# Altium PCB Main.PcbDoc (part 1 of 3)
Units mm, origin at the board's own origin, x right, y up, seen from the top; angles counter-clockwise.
Board outline 160.02 x 109 mm, 4 copper layers (Top Layer, MidLayer1, MidLayer2, Bottom Layer), stack 1.588 mm thick; 321 components, 271 nets, 1178 pads, 515 vias.
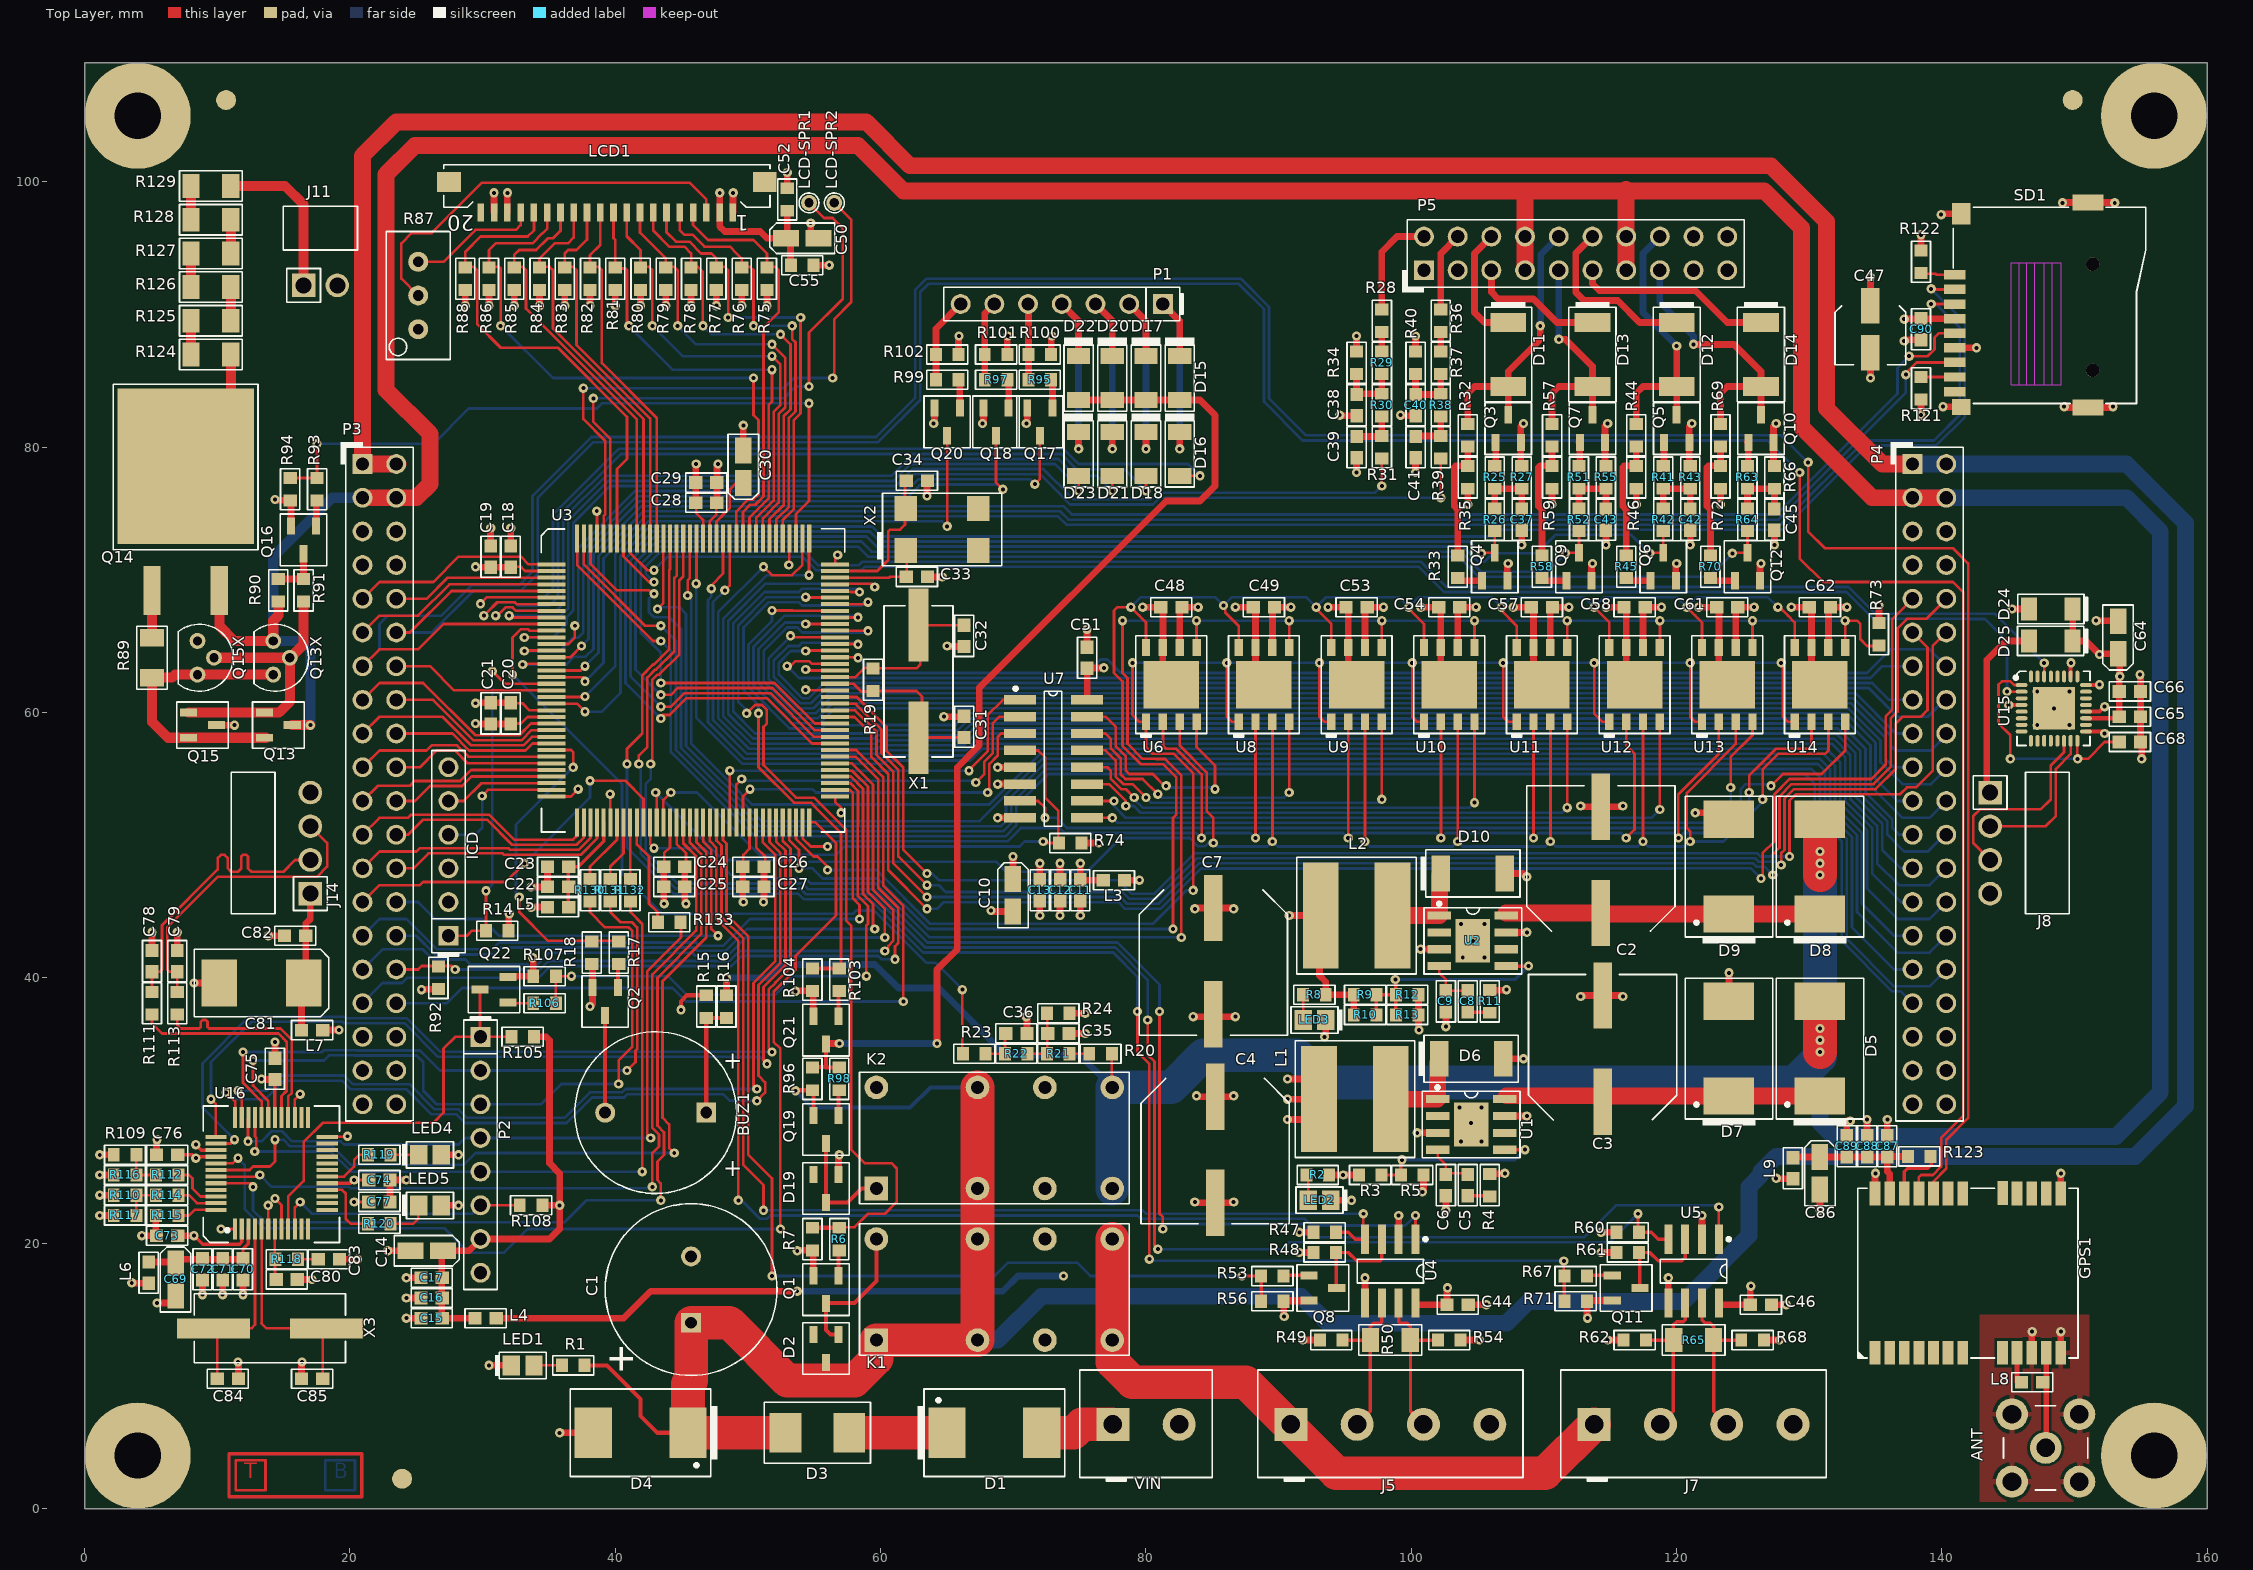
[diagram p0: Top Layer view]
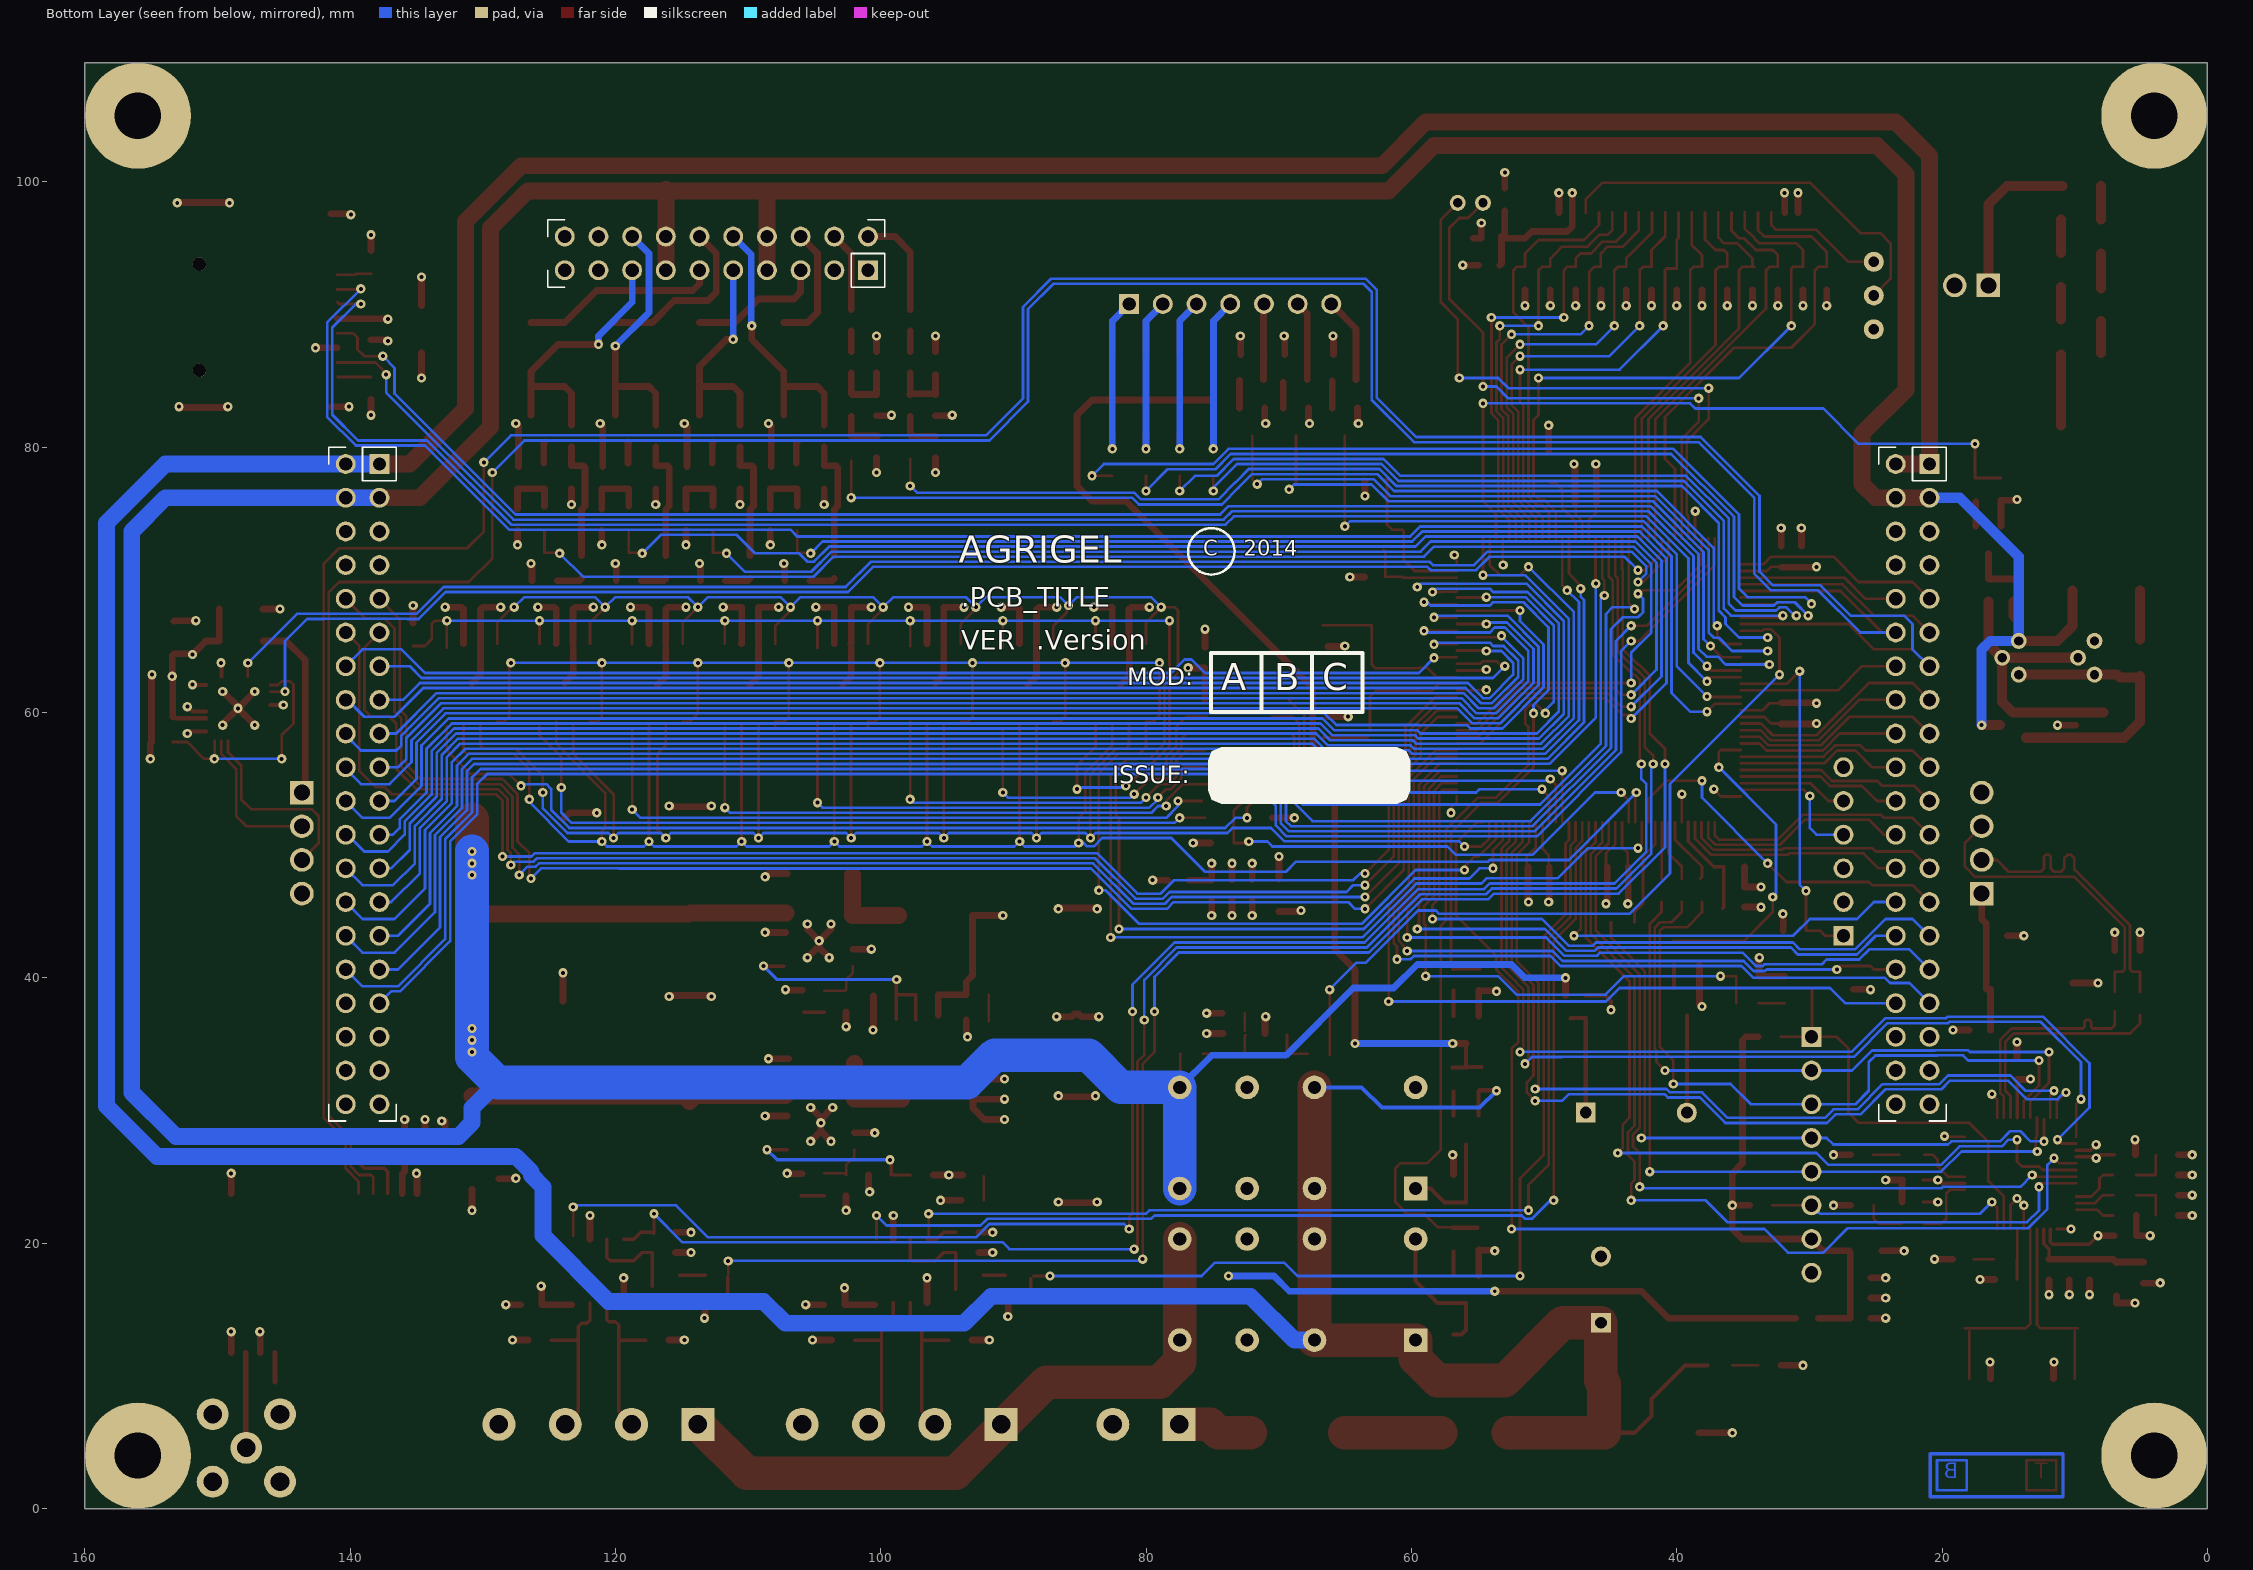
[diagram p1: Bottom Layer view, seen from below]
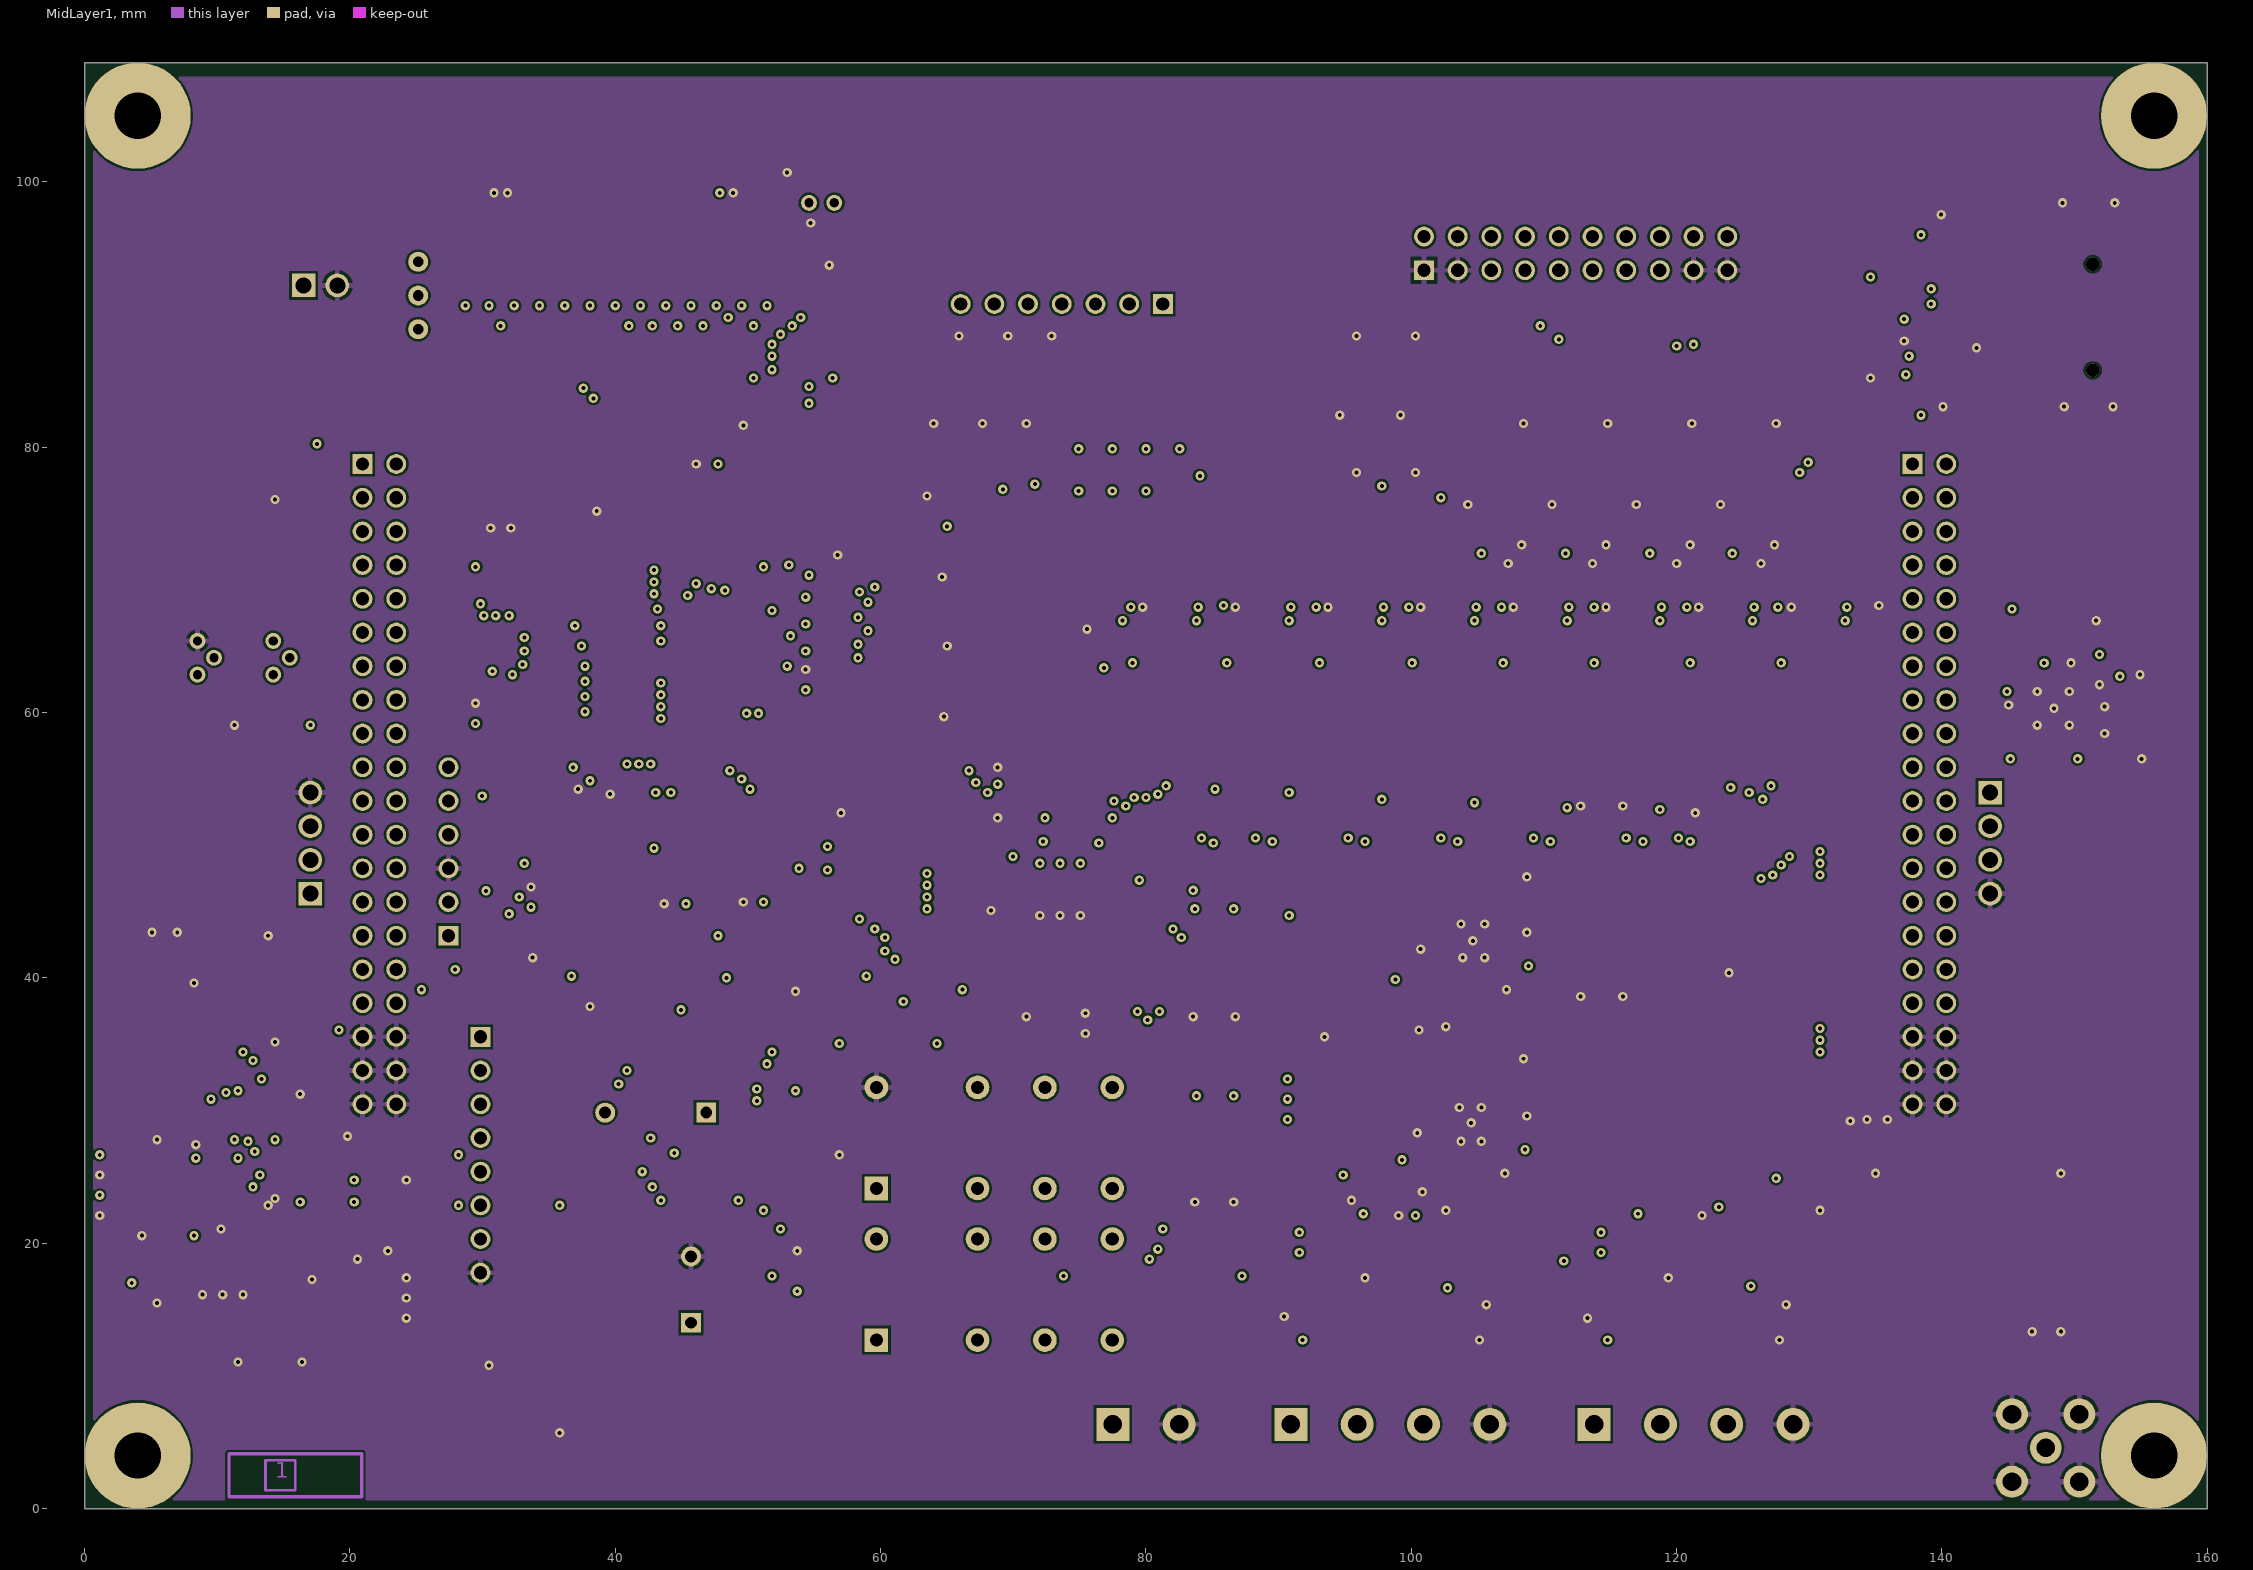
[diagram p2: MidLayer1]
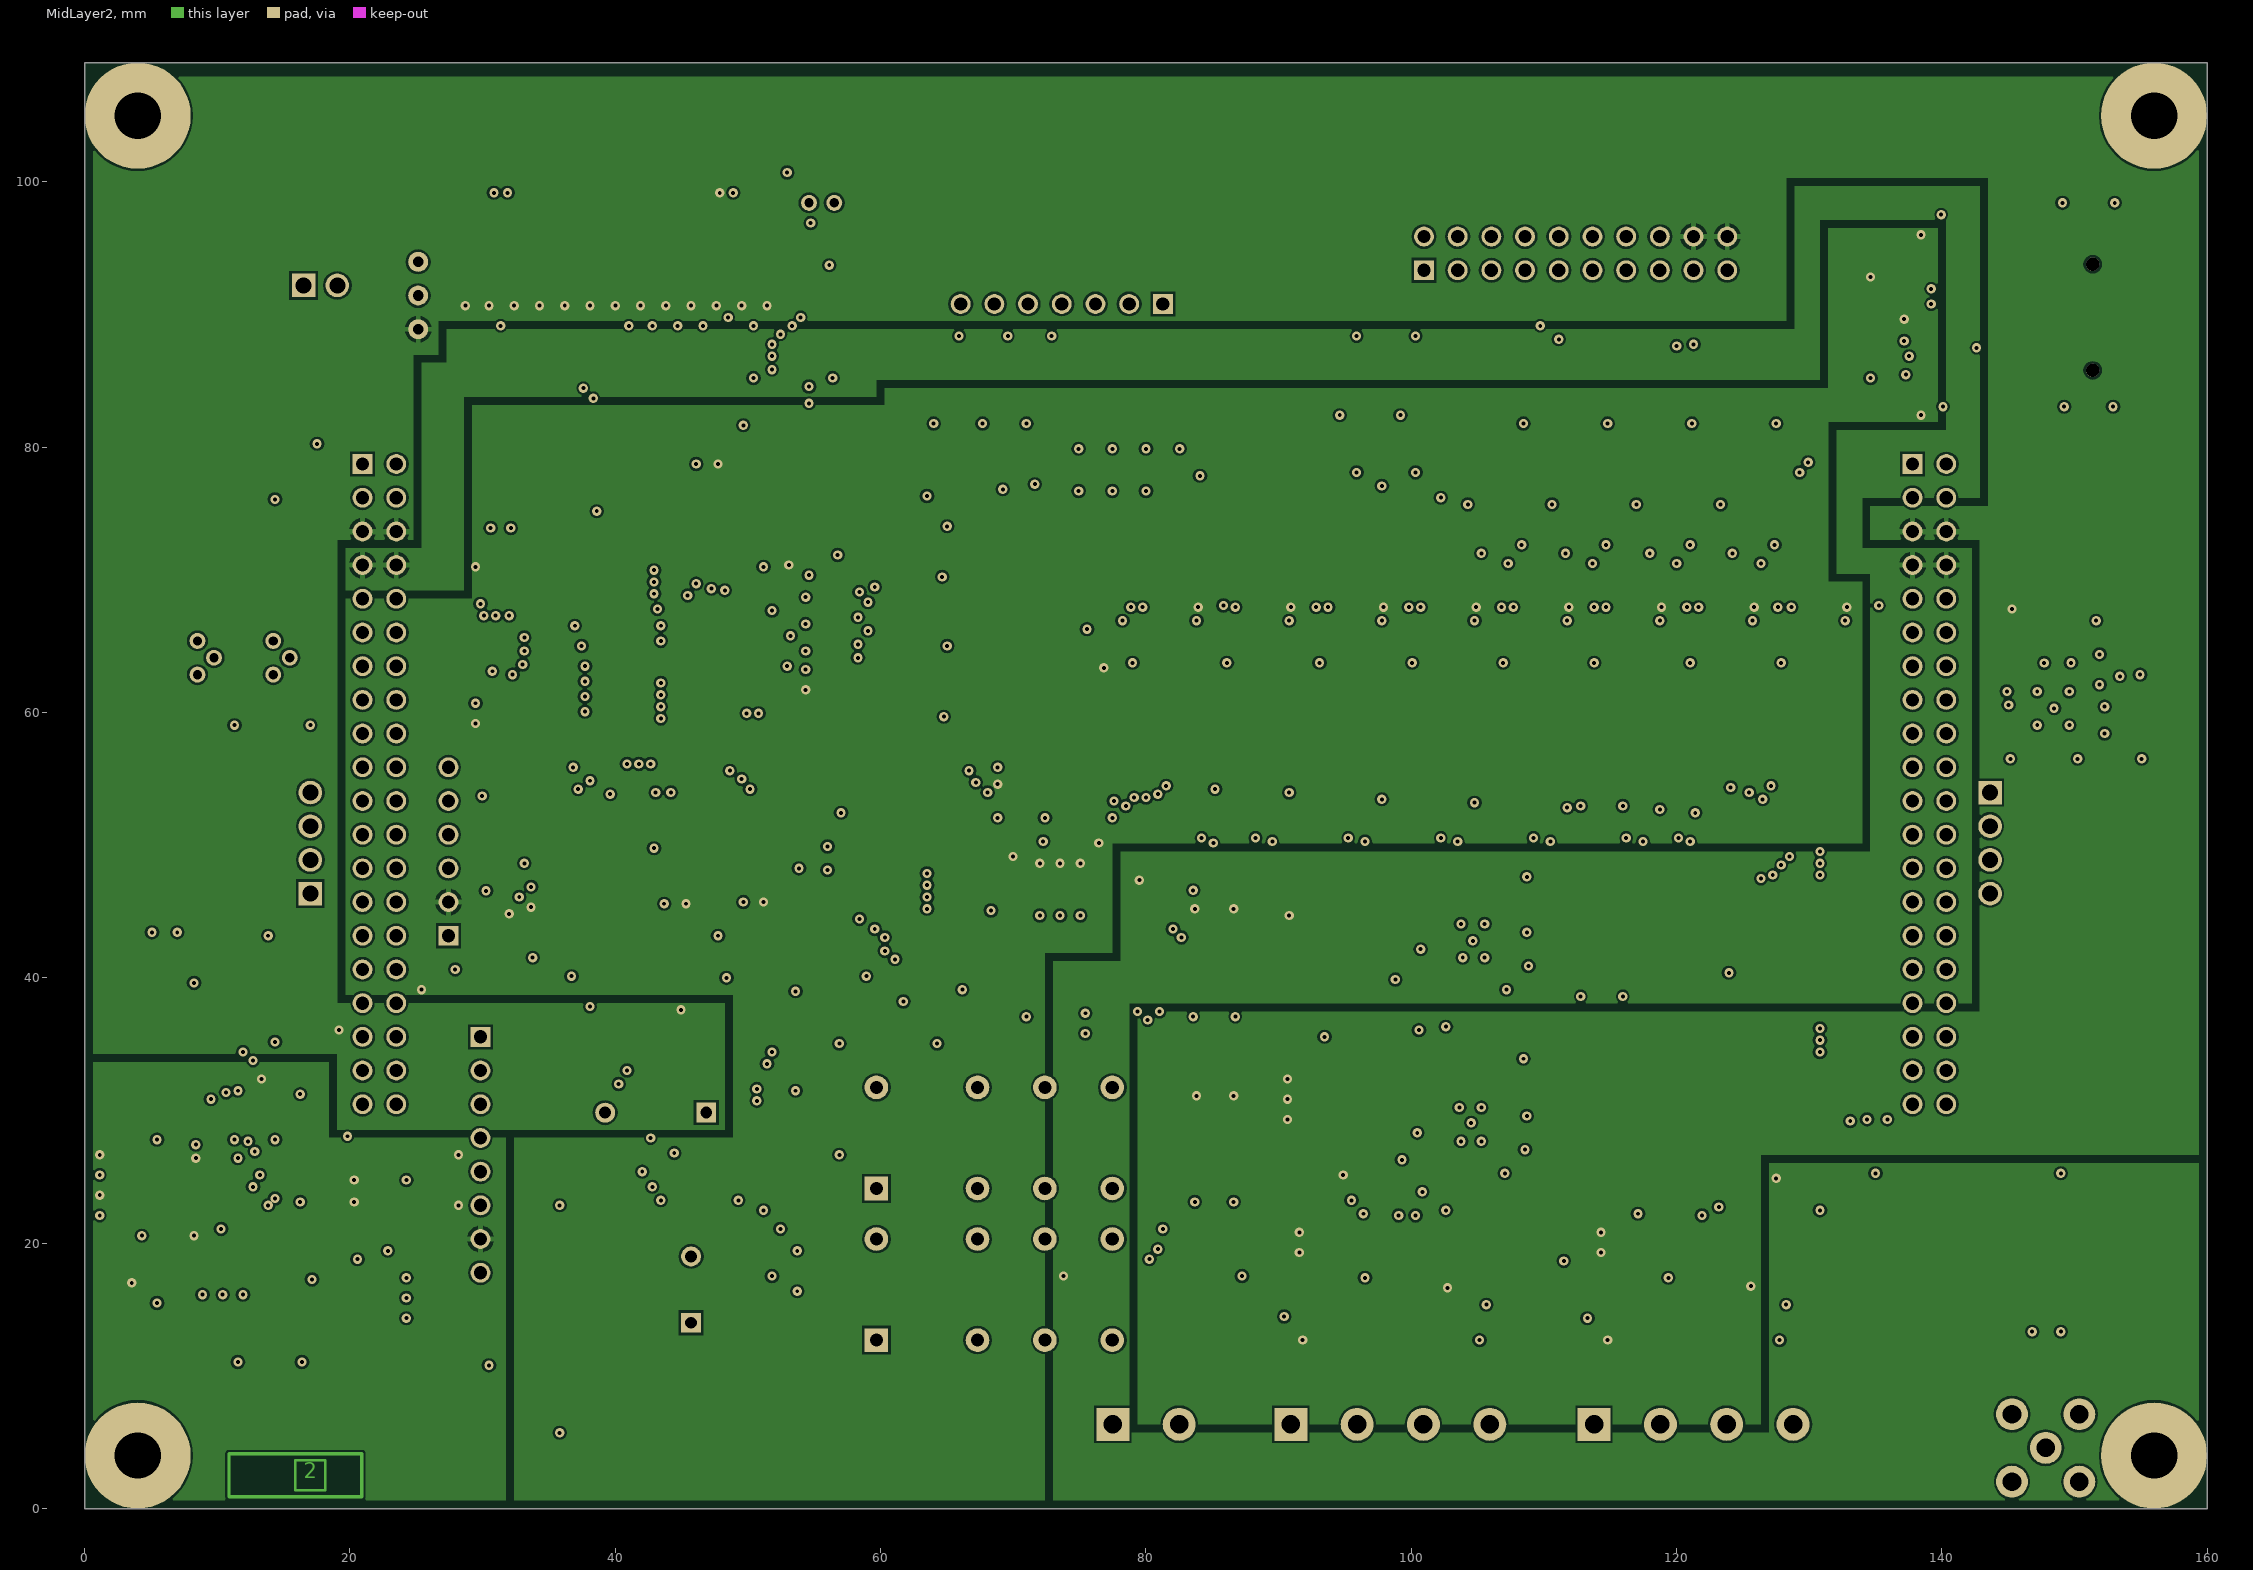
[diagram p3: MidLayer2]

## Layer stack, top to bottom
Top Layer: signal copper 0.0356
Dielectric: prepreg 0.238, FR-4, Dk 4.2
MidLayer1: signal copper 0.0356
Dielectric: core 0.97, FR-4, Dk 4.8
MidLayer2: signal copper 0.0356
Dielectric: prepreg 0.238, FR-4, Dk 4.8
Bottom Layer: signal copper 0.0356

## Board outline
0,0 0,109 160.02,109 160.02,0

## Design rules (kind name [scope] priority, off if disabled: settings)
Clearance Clearance_1 [InNamedPolygon('Top - GND')] p1: gap=0.178
Clearance [All] p2: gap=0.178
FabricationTestPointUsage TestPointUsage [All] p1: valid=0 allowmultiple=FALSE
FabricationTestpoint Testpoint [All] p1: side=3 testpointundercomponent=TRUE minsize=1.016 maxsize=2.54 preferedsize=1.524 minholesize=0 maxholesize=1.016 preferedholesize=0.813 testpointgrid=0.025 allowsidetop=TRUE allowsidebottom=TRUE usegrid=TRUE gridtolerance=0
HoleSize [All] p1: absolutevalues=TRUE maxlimit=5 minlimit=0.25 maxpercent=80.000 minpercent=20.000
PlaneClearance [All] p1: clearance=0.5
PolygonConnect PolygonConnectVia [All vs isvia] p1: connectstyle=Direct reliefconductorwidth=0.25 reliefentries=4 polygonreliefangle="90 Angle" airgapwidth=0.254
PolygonConnect [All] p2: connectstyle=Relief reliefconductorwidth=0.4 reliefentries=4 polygonreliefangle="90 Angle" airgapwidth=0.254
RoutingCorners [All] p1: cornerstyle=45-Degree minsetback=2.5 maxsetback=2.5
RoutingLayers [All] p1: top layer_v5=TRUE mid layer 1_v5=FALSE mid layer 2_v5=FALSE bottom layer_v5=TRUE
RoutingVias [All] p1: holewidth=0.3 width=0.7 viastyle="Through Hole" minholewidth=0.3 minwidth=0.7 maxholewidth=0.3 maxwidth=0.7
SilkToSolderMaskClearance SilkscreenOverComponentPads [IsPad] p1: minsilkscreentomaskgap=0.254 clearancetoexposedcopper=TRUE
SolderMaskExpansion [All] p1: expansion=0.05
Width "Width_High Power" [InNetClass('High Power')] p1: maxlimit=1.5 minlimit=0.5 preferedwidth=1
Width Width_Power [InNetClass('Power')] p2: maxlimit=1 minlimit=0.3 preferedwidth=0.5
Width [All] p3: maxlimit=2.54 minlimit=0.178 preferedwidth=0.203
21 further rules are at their usual default settings.

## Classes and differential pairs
component class Main-1: C1 C2 C3 C4 C5 C6 C7 C8 C9 C10 C11 C12 C13 C14 C15 C16 C17 D1 D2 D3 D4 D5 D6 D7 D8 D9 D10 K1 L1 L2 L3 L4 LED1 LED2 LED3 Q1 R1 R2 R3 R4 R5 R6 R7 R8 R9 R10 R11 R12 R13 U1 U2 VIN
component class Main-2: BUZ1 C18 C19 C20 C21 C22 C23 C24 C25 C26 C27 C28 C29 C30 C31 C32 C33 C34 ICD L5 Q2 R14 R15 R16 R17 R18 R19 R92 U3 X1 X2
component class Main-3: C35 C36 C37 C38 C39 C40 C41 C42 C43 C44 C45 C46 D11 D12 D13 D14 J5 J7 P5 Q3 Q4 Q5 Q6 Q7 Q8 Q9 Q10 Q11 Q12 R20 R21 R22 R23 R24 R25 R26 R27 R28 R29 R30 R31 R32 R33 R34 R35 R36 R37 R38 R39 R40 R41 R42 R43 R44 R45 R46 R47 R48 R49 R50 R51 R52 R53 R54 R55 R56 R57 R58 R59 R60 R61 R62 R63 R64 R65 R66 R67 R68 R69 R70 R71 R72 U4 U5
component class Main-4: C48 C49 C51 C53 C54 C57 C58 C61 C62 R73 R74 U6 U7 U8 U9 U10 U11 U12 U13 U14
component class Main-5: C50 C52 C55 C64 C65 C66 C68 D15 D16 D17 D18 D19 D20 D21 D22 D23 D24 D25 J8 J11 K2 LCD1 LCD-SPR1 LCD-SPR2 P1 Q13 Q13X Q14 Q15 Q15X Q16 Q17 Q18 Q19 Q20 Q21 R75 R76 R77 R78 R79 R80 R81 R82 R83 R84 R85 R86 R87 R88 R89 R90 R91 R93 R94 R95 R96 R97 R98 R99 R100 R101 R102 R103 R104 R124 R125 R126 R127 R128 R129 U15
component class Main-6: ANT C47 C69 C70 C71 C72 C73 C74 C75 C76 C77 C78 C79 C80 C81 C82 C83 C84 C85 C86 C87 C88 C89 C90 GPS1 J14 L6 L7 L8 L9 LED4 LED5 P2 Q22 R105 R106 R107 R108 R109 R110 R111 R112 R113 R114 R115 R116 R117 R118 R119 R120 R121 R122 R123 R130 R131 R132 R133 SD1 U16 X3
component class Main-7: P3 P4

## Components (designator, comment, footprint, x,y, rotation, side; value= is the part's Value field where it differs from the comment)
ANT "Coax-MCX-RT" MCX-RT-733660030 147.828,4.572 r90 top
BUZ1 "MBS-03" Buzzer-MBS01-12 43.053,29.845 r0 top
C1 "CAP-EL_1000uF_35V_20%-YXF" EL-RAD-12.5x20 45.72,16.51 r180 top
C2 "100uF35V-20%-EEVFC" CAP-EL-SMD-10x10.5 114.3,48.895 r90 top
C3 "100uF35V-20%-EEVFC" CAP-EL-SMD-10x10.5 114.427,34.671 r90 top
C4 "470uF-35V-20%-LZ" CAP-EL-SMD-10x10.5 85.217,27.051 r270 top
C5 "22nF_C0603_50V_10%_X7R" CAPC0603X85N#1 104.267,24.384 r270 top
C6 "220pF_C0603_50V_10%_NP0" CAPC0603X85N#1 102.616,24.384 r270 top
C7 "470uF-35V-20%-LZ" CAP-EL-SMD-10x10.5 85.09,41.275 r270 top
C8 "22nF_C0603_50V_10%_X7R" CAPC0603X85N#1 104.267,38.227 r270 top
C9 "220pF_C0603_50V_10%_NP0" CAPC0603X85N#1 102.616,38.227 r270 top
C10 "10uF_6.3V_T491A_20%" T491-A 69.977,46.228 r270 top
C11 "1.0nF_C0603_50V_10%_X7R" CAPC0603X85N#1 75.057,46.609 r270 top
C12 "10nF_C0603_50V_10%_X7R" CAPC0603X85N#1 73.533,46.609 r270 top
C13 "100nF_C0603_50V_5%_X7R" CAPC0603X85N#1 72.009,46.609 r270 top
C14 "10uF_6.3V_T491A_20%" T491-A 25.781,19.431 r180 top
C15 "1.0nF_C0603_50V_10%_X7R" CAPC0603X85N#1 26.162,14.351 r180 top
C16 "10nF_C0603_50V_10%_X7R" CAPC0603X85N#1 26.162,15.875 r180 top
C17 "100nF_C0603_50V_5%_X7R" CAPC0603X85N#1 26.162,17.399 r180 top
C18 "10nF_C0603_50V_10%_X7R" CAPC0603X85N#1 32.131,71.755 r90 top
C19 "100nF_C0603_50V_5%_X7R" CAPC0603X85N#1 30.607,71.755 r90 top
C20 "10nF_C0603_50V_10%_X7R" CAPC0603X85N#1 32.131,59.944 r90 top
C21 "100nF_C0603_50V_5%_X7R" CAPC0603X85N#1 30.607,59.944 r90 top
C22 "1.0nF_C0603_50V_10%_X7R" CAPC0603X85N#1 35.687,46.863 r180 top
C23 "100nF_C0603_50V_5%_X7R" CAPC0603X85N#1 35.687,48.387 r180 top
C24 "10nF_C0603_50V_10%_X7R" CAPC0603X85N#1 44.45,48.387 r180 top
C25 "100nF_C0603_50V_5%_X7R" CAPC0603X85N#1 44.45,46.863 r180 top
C26 "10nF_C0603_50V_10%_X7R" CAPC0603X85N#1 50.419,48.387 r180 top
C27 "100nF_C0603_50V_5%_X7R" CAPC0603X85N#1 50.419,46.863 r180 top
C28 "10nF_C0603_50V_10%_X7R" CAPC0603X85N#1 46.863,75.819 r180 top
C29 "100nF_C0603_50V_5%_X7R" CAPC0603X85N#1 46.863,77.343 r180 top
C30 "10uF_6.3V_T491A_20%" T491-A 49.657,78.531 r90 top
C31 "15pF_C0603_50V_5%_NP0" CAPC0603X85N#1 66.294,58.928 r90 top
C32 "15pF_C0603_50V_5%_NP0" CAPC0603X85N#1 66.294,65.786 r270 top
C33 "DNF_C0603_50V_10%_X7R" CAPC0603X85N#1 62.738,70.231 r0 top
C34 "DNF_C0603_50V_10%_X7R" CAPC0603X85N#1 62.738,77.47 r0 top
C35 "100nF_C0603_50V_5%_X7R" CAPC0603X85N#1 73.406,35.814 r0 top
C36 "100nF_C0603_50V_5%_X7R" CAPC0603X85N#1 70.231,35.814 r0 top
C37 "150pF_C0603_50V_5%_NP0" CAPC0603X85N#1 108.331,74.549 r270 top
C38 "100nF_C0603_50V_5%_X7R" CAPC0603X85N#1 95.885,83.185 r270 top
C39 "100nF_C0603_50V_5%_X7R" CAPC0603X85N#1 95.885,80.01 r270 top
C40 "100nF_C0603_50V_5%_X7R" CAPC0603X85N#1 100.33,83.185 r270 top
C41 "100nF_C0603_50V_5%_X7R" CAPC0603X85N#1 100.33,80.01 r270 top
C42 "150pF_C0603_50V_5%_NP0" CAPC0603X85N#1 121.031,74.549 r270 top
C43 "DNF_C0603_50V_10%_X7R" CAPC0603X85N#1 114.681,74.549 r270 top
C44 "100nF_C0603_50V_5%_X7R" CAPC0603X85N#1 103.505,15.367 r0 top
C45 "DNF_C0603_50V_10%_X7R" CAPC0603X85N#1 127.381,74.549 r270 top
C46 "100nF_C0603_50V_5%_X7R" CAPC0603X85N#1 126.365,15.367 r0 top
C47 "2.2uF-50V-20%_4x5.4" CAP-EL-SMD-4X5.4 134.62,88.9 r270 top
C48 "100nF_C0603_50V_5%_X7R" CAPC0603X85N#1 81.915,67.945 r180 top
C49 "10nF_C0603_50V_10%_X7R" CAPC0603X85N#1 88.9,67.945 r180 top
C50 "4.7uF_6V_T491A_20%" T491-A 54.102,95.758 r0 top
C51 "10nF_C0603_50V_10%_X7R" CAPC0603X85N#1 75.565,64.135 r90 top
C52 "10nF_C0603_50V_10%_X7R" CAPC0603X85N#2 52.959,98.679 r90 top
C53 "100nF_C0603_50V_5%_X7R" CAPC0603X85N#1 95.885,67.945 r180 top
C54 "10nF_C0603_50V_10%_X7R" CAPC0603X85N#1 102.87,67.945 r180 top
C55 "100nF_C0603_50V_5%_X7R" CAPC0603X85N#2 54.102,93.726 r0 top
C57 "100nF_C0603_50V_5%_X7R" CAPC0603X85N#1 109.855,67.945 r180 top
C58 "10nF_C0603_50V_10%_X7R" CAPC0603X85N#1 116.84,67.945 r180 top
C61 "100nF_C0603_50V_5%_X7R" CAPC0603X85N#1 123.825,67.945 r180 top
C62 "10nF_C0603_50V_10%_X7R" CAPC0603X85N#1 130.81,67.945 r180 top
C64 "4.7uF_6V_T491A_20%" T491-A 153.289,65.659 r90 top
C65 "10nF_C0603_50V_10%_X7R" CAPC0603X85N#1 154.178,59.69 r0 top
C66 "100nF_C0603_50V_5%_X7R" CAPC0603X85N#1 154.178,61.595 r0 top
C68 "100nF_C0603_50V_5%_X7R" CAPC0603X85N#1 154.178,57.785 r0 top
C69 "10uF_6.3V_T491A_20%" T491-A 6.858,17.272 r270 top
C70 "1.0nF_C0603_50V_10%_X7R" CAPC0603X85N#1 11.938,18.034 r270 top
C71 "10nF_C0603_50V_10%_X7R" CAPC0603X85N#1 10.414,18.034 r270 top
C72 "100nF_C0603_50V_5%_X7R" CAPC0603X85N#1 8.89,18.034 r270 top
C73 "100nF_C0603_50V_5%_X7R" CAPC0603X85N#1 6.223,20.574 r180 top
C74 "100nF_C0603_50V_5%_X7R" CAPC0603X85N#1 22.225,24.765 r0 top
C75 "100nF_C0603_50V_5%_X7R" CAPC0603X85N#1 14.351,33.147 r90 top
C76 "100nF_C0603_50V_5%_X7R" CAPC0603X85N#1 6.223,26.67 r180 top
C77 "100nF_C0603_50V_5%_X7R" CAPC0603X85N#1 22.225,23.114 r0 top
C78 "47pF_C0603_50V_10%_NP0" CAPC0603X85N#1 5.08,41.275 r90 top
C79 "47pF_C0603_50V_10%_NP0" CAPC0603X85N#1 6.985,41.275 r90 top
C80 "1.0nF_C0603_50V_10%_X7R" CAPC0603X85N#1 15.24,17.272 r0 top
C81 "47uF_25V_T491D_20%" T491-D 13.335,39.624 r180 top
C82 "100nF_C0603_50V_5%_X7R" CAPC0603X85N#1 15.875,43.18 r180 top
C83 "10nF_C0603_50V_10%_X7R" CAPC0603X85N#1 18.415,18.796 r0 top
C84 "10pF_C0603_50V_5%_NP0" CAPC0603X85N#1 10.795,9.779 r0 top
C85 "10pF_C0603_50V_5%_NP0" CAPC0603X85N#1 17.145,9.779 r180 top
C86 "10uF_6.3V_T491A_20%" T491-A 130.81,25.273 r270 top
C87 "1.0nF_C0603_50V_10%_X7R" CAPC0603X85N#1 135.89,27.305 r90 top
C88 "10nF_C0603_50V_10%_X7R" CAPC0603X85N#1 134.366,27.305 r90 top
C89 "100nF_C0603_50V_5%_X7R" CAPC0603X85N#1 132.842,27.305 r90 top
C90 "100nF_C0603_50V_5%_X7R" CAPC0603X85N#1 138.43,88.9 r270 top
D1 "ER3M" SMC 68.58,5.715 r0 top
D2 "BAS16" SOT23 55.88,12.065 r270 top
D3 "0157003.DRT" LF-0157 55.245,5.715 r180 top
D4 "SMCJ26A" SMC 41.91,5.715 r180 top
D5 "ER3M" SMC 130.81,34.671 r90 top
D6 "SMS2100" DO-213AB 104.521,33.909 r0 top
D7 "SMCJ26A" SMC 123.952,34.671 r90 top
D8 "ER3M" SMC 130.81,48.387 r90 top
D9 "SMCJ26A" SMC 123.952,48.387 r90 top
D10 "SMS2100" DO-213AB 104.648,47.879 r0 top
D11 "SM4007" DO-213AB 107.315,86.995 r270 top
D12 "SM4007" DO-213AB 120.015,86.995 r270 top
D13 "SM4007-DNF" DO-213AB 113.665,86.995 r270 top
D14 "SM4007-DNF" DO-213AB 126.365,86.995 r270 top
D15 "LL4148" SOD80 82.55,85.217 r90 top
D16 "LL4148" SOD80 82.55,79.502 r90 top
D17 "LL4148" SOD80 80.01,85.217 r90 top
D18 "LL4148" SOD80 80.01,79.502 r90 top
D19 "BAS16" SOT23 55.88,24.13 r270 top
D20 "LL4148" SOD80 77.47,85.217 r90 top
D21 "LL4148" SOD80 77.47,79.502 r90 top
D22 "LL4148" SOD80 74.93,85.217 r90 top
D23 "LL4148" SOD80 74.93,79.502 r90 top
D24 "LL4148" SOD80 148.213,67.811 r0 top
D25 "LL4148" SOD80 148.209,65.405 r0 top
GPS1 "S1216R" S1216R 141.986,17.399 r90 top
ICD "SIL6P-2.54" SIL6P-2.54 27.432,49.53 r90 top
J5 "8191-4-5.0" SCREW-TB-4-5.0 98.425,6.35 r0 top
J7 "8191-4-5.0" SCREW-TB-4-5.0 121.285,6.35 r0 top
J8 "M7395-4" M7395-4 147.955,50.165 r90 top
J11 "M7395-2" M7395-2 17.78,96.52 r180 top
J14 "M7395-4" M7395-4 12.7,50.165 r270 top
K1 "V23105-A5003-A201-12V" REL-D2n 68.58,16.51 r90 top
K2 "V23105-A5003-A201-12V" REL-D2n 68.58,27.94 r90 top
L1 "SDR0805-330K" SDR0805 95.758,30.861 r180 top
L2 "SDR0805-330K" SDR0805 95.885,44.704 r180 top
L3 "100nH-CI160808" L0603 77.597,47.371 r180 top
L4 "100nH-CI160808" L0603 30.226,14.351 r180 top
L5 "100nH-CI160808" L0603 35.687,45.339 r180 top
L6 "100nH-CI160808" L0603 4.826,17.78 r90 top
L7 "100nH-CI160808" L0603 17.145,36.068 r0 top
L8 "33nH-0603CS" L0603CS 146.812,9.525 r180 top
L9 "100nH-CI160808" L0603 128.778,25.654 r270 top
LCD1 "FPC3AMR1-20TNBT-U-Bottom" FPC3AMR1-20-B-U 39.37,99.695 r180 top
LCD-SPR1 "TP-THP-0.7MM" TP-THP-0.7mm 54.61,98.425 r90 top
LCD-SPR2 "TP-THP-0.7MM" TP-THP-0.7mm 56.515,98.425 r90 top
LED1 "RED_0805_SMD" LED0805-Red 33.02,10.795 r0 top
LED2 "GREEN_0805_SMD" LED0805-Green 93.091,23.241 r180 top
LED3 "YELLOW_0805_SMD" LED0805-Yellow 92.71,36.83 r180 top
LED4 "RED_0805_SMD" LED0805-Red 26.035,26.67 r0 top
LED5 "GREEN_0805_SMD" LED0805-Green 26.035,22.86 r0 top
P1 "SIL7P-2.54" SIL7P-2.54 73.66,90.805 r180 top
P2 "SIL8P-2.54" SIL8P-2.54 29.845,26.67 r270 top
P3 "DIL40P-2.54-DNF" DIL40-P-2.54 22.225,54.61 r270 top
P4 "DIL40P-2.54-DNF" DIL40-P-2.54 139.065,54.61 r270 top
P5 "DIL20P-2.54-DNF" DIL20-P-2.54 112.395,94.615 r0 top
Q1 "BC817" SOT23 55.88,16.51 r270 top
Q2 "BC817" SOT23 39.243,38.227 r270 top
Q3 "BC817" SOT23 107.315,81.407 r90 top
Q4 "BC817-DNF" SOT23 106.299,70.993 r90 top
Q5 "BC817" SOT23 120.015,81.407 r90 top
Q6 "BC817-DNF" SOT23 118.999,70.993 r90 top
Q7 "BC817-DNF" SOT23 113.665,81.407 r90 top
Q8 "BC817" SOT23 93.345,16.637 r0 top
Q9 "BC817" SOT23 112.649,70.993 r90 top
Q10 "BC817-DNF" SOT23 126.365,81.407 r90 top
Q11 "BC817" SOT23 116.205,16.637 r0 top
Q12 "BC817" SOT23 125.349,70.993 r90 top
Q13 "BC817" SOT23 14.605,59.055 r0 top
Q13X "BC337-DNF" TO-92 13.97,64.135 r270 top
Q14 "IRF9530NS" D2PAK 7.62,75.565 r90 top
Q15 "BC807" SOT23 8.89,59.055 r0 top
Q15X "BC327-DNF" TO-92 8.255,64.135 r270 top
Q16 "BC817" SOT23 16.51,73.025 r270 top
Q17 "BC817" SOT23 72.009,81.915 r270 top
Q18 "BC817" SOT23 68.707,81.915 r270 top
Q19 "BC807" SOT23 55.88,28.575 r270 top
Q20 "BC817" SOT23 65.024,81.915 r270 top
Q21 "BC817" SOT23 55.88,36.068 r270 top
Q22 "BC817" SOT23 30.861,39.116 r180 top
R1 "10K_R0603_1%" RESC0603X60N 36.83,10.795 r180 top
R2 "470R_R0603_1%" RESC0603X60N 92.964,25.146 r180 top
R3 "10K_R0603_1%" RESC0603X60N 96.901,25.146 r0 top
R4 "4K7_R0603_1%" RESC0603X60N 105.918,24.384 r90 top
R5 "3K3_R0603_1%" RESC0603X60N 100.076,25.146 r0 top
R6 "2K2_R0603_1%" RESC0603X60N 56.896,20.32 r270 top
R7 "10K_R0603_1%" RESC0603X60N 54.864,20.32 r270 top
R8 "470R_R0603_1%" RESC0603X60N 92.71,38.735 r180 top
R9 "5K6_R0603_1%" RESC0603X60N 96.52,38.735 r0 top
R10 "DNF_R0603_1%" RESC0603X60N 96.52,37.211 r0 top
R11 "4K7_R0603_1%" RESC0603X60N 105.918,38.227 r90 top
R12 "3K3_R0603_1%" RESC0603X60N 99.695,38.735 r0 top
R13 "DNF_R0603_1%" RESC0603X60N 99.695,37.211 r0 top
R14 "10K_R0603_1%" RESC0603X60N 31.115,43.561 r180 top
R15 "0R_R0603_1%" RESC0603X60N 46.863,37.846 r270 top
R16 "0R_R0603_1%" RESC0603X60N 48.387,37.846 r270 top
R17 "2K2_R0603_1%" RESC0603X60N 40.259,41.91 r270 top
R18 "10K_R0603_1%" RESC0603X60N 38.227,41.91 r270 top
R19 "1M_R0603_1%" RESC0603X60N 59.436,62.484 r90 top
R20 "1K8_R0603_1%" RESC0603X60N 76.581,34.29 r180 top
R21 "1K8_R0603_1%" RESC0603X60N 73.406,34.29 r180 top
R22 "1K_R0603_1%" RESC0603X60N 70.231,34.29 r180 top
R23 "1K_R0603_1%" RESC0603X60N 67.056,34.29 r180 top
R24 "1K_R0603_1%" RESC0603X60N 73.406,37.338 r0 top
R25 "2K2_R0603_1%" RESC0603X60N 106.299,77.724 r270 top
R26 "390R_R0603_1%" RESC0603X60N 106.299,74.549 r270 top
R27 "10K_R0603_1%" RESC0603X60N 108.331,77.724 r90 top
R28 "1K8_R0603_1%" RESC0603X60N 97.79,89.535 r270 top
R29 "1K8_R0603_1%" RESC0603X60N 97.79,86.36 r270 top
R30 "1K_R0603_1%" RESC0603X60N 97.79,83.185 r270 top
R31 "1K_R0603_1%" RESC0603X60N 97.79,80.01 r270 top
R32 "DNP_R0603_1%" RESC0603X60N 104.267,80.899 r270 top
R33 "DNP_R0603_1%" RESC0603X60N 103.505,70.993 r270 top
R34 "1K_R0603_1%" RESC0603X60N 95.885,86.36 r90 top
R35 "DNP_R0603_1%" RESC0603X60N 104.267,77.724 r270 top
R36 "1K8_R0603_1%" RESC0603X60N 102.235,89.535 r270 top
R37 "1K8_R0603_1%" RESC0603X60N 102.235,86.36 r270 top
R38 "1K_R0603_1%" RESC0603X60N 102.235,83.185 r270 top
R39 "1K_R0603_1%" RESC0603X60N 102.235,80.01 r270 top
R40 "1K_R0603_1%" RESC0603X60N 100.33,86.36 r90 top
R41 "2K2_R0603_1%" RESC0603X60N 118.999,77.724 r270 top
R42 "390R_R0603_1%" RESC0603X60N 118.999,74.549 r270 top
R43 "10K_R0603_1%" RESC0603X60N 121.031,77.724 r90 top
R44 "DNP_R0603_1%" RESC0603X60N 116.967,80.899 r270 top
R45 "DNP_R0603_1%" RESC0603X60N 116.205,70.993 r270 top
R46 "DNP_R0603_1%" RESC0603X60N 116.967,77.724 r270 top
R47 "3K3_R0603_1%" RESC0603X60N 93.472,20.828 r0 top
R48 "3K3_R0603_1%" RESC0603X60N 93.472,19.304 r0 top
R49 "560R_R0603_1%" RESC0603X60N 93.98,12.7 r0 top
R50 "120R_R1206_1%-DNF" RESC1206X71N 98.425,12.7 r0 top
R51 "DNP_R0603_1%" RESC0603X60N 112.649,77.724 r270 top
R52 "DNP_R0603_1%" RESC0603X60N 112.649,74.549 r270 top
R53 "2K2_R0603_1%" RESC0603X60N 89.535,17.526 r0 top
R54 "560R_R0603_1%" RESC0603X60N 102.87,12.7 r0 top
R55 "DNP_R0603_1%" RESC0603X60N 114.681,77.724 r90 top
R56 "10K_R0603_1%" RESC0603X60N 89.535,15.621 r0 top
R57 "0R_R0603_1%" RESC0603X60N 110.617,80.899 r270 top
R58 "4K7_R0603_1%" RESC0603X60N 109.855,70.993 r270 top
R59 "10K_R0603_1%" RESC0603X60N 110.617,77.724 r270 top
R60 "3K3_R0603_1%" RESC0603X60N 116.332,20.828 r0 top
R61 "3K3_R0603_1%" RESC0603X60N 116.332,19.304 r0 top
R62 "560R_R0603_1%" RESC0603X60N 116.84,12.7 r0 top
R63 "DNP_R0603_1%" RESC0603X60N 125.349,77.724 r270 top
R64 "DNP_R0603_1%" RESC0603X60N 125.349,74.549 r270 top
R65 "120R_R1206_1%-DNF" RESC1206X71N 121.285,12.7 r0 top
R66 "DNP_R0603_1%" RESC0603X60N 127.381,77.724 r90 top
R67 "2K2_R0603_1%" RESC0603X60N 112.395,17.526 r0 top
R68 "560R_R0603_1%" RESC0603X60N 125.73,12.7 r0 top
R69 "0R_R0603_1%" RESC0603X60N 123.317,80.899 r270 top
R70 "4K7_R0603_1%" RESC0603X60N 122.555,70.993 r270 top
R71 "10K_R0603_1%" RESC0603X60N 112.395,15.621 r0 top
R72 "10K_R0603_1%" RESC0603X60N 123.317,77.724 r270 top
R73 "10K_R0603_1%" RESC0603X60N 135.255,65.913 r90 top
R74 "10K_R0603_1%" RESC0603X60N 74.295,50.165 r180 top
R75 "10K_R0603_1%" RESC0603X60N 51.435,92.71 r90 top
R76 "10K_R0603_1%" RESC0603X60N 49.53,92.71 r90 top
R77 "10K_R0603_1%" RESC0603X60N 47.625,92.71 r90 top
R78 "10K_R0603_1%" RESC0603X60N 45.72,92.71 r90 top
R79 "10K_R0603_1%" RESC0603X60N 43.815,92.71 r90 top
R80 "10K_R0603_1%" RESC0603X60N 41.91,92.71 r90 top
R81 "10K_R0603_1%" RESC0603X60N 40.005,92.71 r90 top
R82 "10K_R0603_1%" RESC0603X60N 38.1,92.71 r90 top
R83 "10K_R0603_1%" RESC0603X60N 36.195,92.71 r90 top
R84 "10K_R0603_1%" RESC0603X60N 34.29,92.71 r90 top
R85 "10K_R0603_1%" RESC0603X60N 32.385,92.71 r90 top
R86 "10K_R0603_1%" RESC0603X60N 30.48,92.71 r90 top
R87 "3296W-1-103" 3296W-THP 25.146,91.44 r90 top
R88 "10K_R0603_1%" RESC0603X60N 28.702,92.71 r90 top
R89 "10R_R1206_1%" RESC1206X71N 5.08,64.135 r90 top
R90 "10K_R0603_1%" RESC0603X60N 14.605,69.215 r90 top
R91 "4K7_R0603_1%" RESC0603X60N 16.51,69.215 r270 top
R92 "0R_R0603_1%" RESC0603X60N 26.67,40.005 r90 top
R93 "2K2_R0603_1%" RESC0603X60N 17.526,76.835 r270 top
R94 "10K_R0603_1%" RESC0603X60N 15.494,76.835 r270 top
R95 "2K2_R0603_1%" RESC0603X60N 72.009,85.09 r0 top
R96 "10K_R0603_1%" RESC0603X60N 54.864,32.385 r90 top
R97 "2K2_R0603_1%" RESC0603X60N 68.707,85.09 r0 top
R98 "4K7_R0603_1%" RESC0603X60N 56.896,32.385 r90 top
R99 "2K2_R0603_1%" RESC0603X60N 65.024,85.09 r0 top
R100 "10K_R0603_1%" RESC0603X60N 72.009,86.995 r0 top
R101 "10K_R0603_1%" RESC0603X60N 68.707,86.995 r0 top
R102 "10K_R0603_1%" RESC0603X60N 65.024,86.995 r0 top
R103 "2K2_R0603_1%" RESC0603X60N 56.896,39.878 r270 top
R104 "10K_R0603_1%" RESC0603X60N 54.864,39.878 r270 top
R105 "10K_R0603_1%" RESC0603X60N 33.02,35.56 r180 top
R106 "2K2_R0603_1%" RESC0603X60N 34.671,38.1 r180 top
R107 "10K_R0603_1%" RESC0603X60N 34.671,40.132 r180 top
R108 "10K_R0603_1%" RESC0603X60N 33.655,22.86 r180 top
R109 "0R_R0603_1%" RESC0603X60N 3.048,26.67 r0 top
R110 "DNP_R0603_1%" RESC0603X60N 3.048,23.622 r0 top
R111 "27R_R0603_1%" RESC0603X60N 5.08,38.1 r270 top
R112 "47K_R0603_1%" RESC0603X60N 6.223,25.146 r180 top
R113 "27R_R0603_1%" RESC0603X60N 6.985,38.1 r270 top
R114 "47K_R0603_1%" RESC0603X60N 6.223,23.622 r180 top
R115 "47K_R0603_1%" RESC0603X60N 6.223,22.098 r180 top
R116 "DNP_R0603_1%" RESC0603X60N 3.048,25.146 r180 top
R117 "0R_R0603_1%" RESC0603X60N 3.048,22.098 r180 top
R118 "180R_R0603_1%" RESC0603X60N 15.24,18.796 r0 top
R119 "330R_R0603_1%" RESC0603X60N 22.225,26.67 r0 top
R120 "330R_R0603_1%" RESC0603X60N 22.225,21.463 r0 top
R121 "10K_R0603_1%" RESC0603X60N 138.43,84.455 r90 top
R122 "10K_R0603_1%" RESC0603X60N 138.43,93.98 r270 top
R123 "0R_R0603_1%" RESC0603X60N 138.303,26.543 r180 top
R124 "15R_R1206_1%" RESC1206X71N 9.525,86.995 r180 top
R125 "15R_R1206_1%" RESC1206X71N 9.525,89.535 r0 top
R126 "15R_R1206_1%" RESC1206X71N 9.525,92.075 r180 top
R127 "15R_R1206_1%" RESC1206X71N 9.525,94.615 r0 top
R128 "15R_R1206_1%" RESC1206X71N 9.525,97.155 r180 top
R129 "15R_R1206_1%" RESC1206X71N 9.525,99.695 r0 top
R130 "0R_R0603_1%" RESC0603X60N 38.1,46.609 r90 top
R131 "0R_R0603_1%" RESC0603X60N 39.624,46.609 r90 top
R132 "0R_R0603_1%" RESC0603X60N 41.148,46.609 r90 top
R133 "0R_R0603_1%" RESC0603X60N 44.069,44.196 r180 top
SD1 "SD-40BD-10" SD-40BD-10 147.32,90.805 r90 top
U1 "L5973D-HSOP8" HSOP8 104.521,28.956 r0 top
U2 "L5973D-HSOP8" HSOP8 104.648,42.799 r0 top
U3 "PIC24EP512GU814-I/PL" LQFP144-20x20 45.847,62.484 r0 top
U4 "DS75176BM" SO8 98.425,17.907 r270 top
U5 "DS75176BM" SO8 121.285,17.907 r270 top
U6 "AT45DB641E-MWHN" UDFN8-6x5-EP 81.915,62.103 r90 top
U7 "74LVC138AD" SO16 73.025,56.515 r0 top
U8 "AT45DB641E-MWHN" UDFN8-6x5-EP 88.9,62.103 r90 top
U9 "AT45DB641E-MWHN" UDFN8-6x5-EP 95.885,62.103 r90 top
U10 "AT45DB641E-MWHN" UDFN8-6x5-EP 102.87,62.103 r90 top
U11 "AT45DB641E-MWHN" UDFN8-6x5-EP 109.855,62.103 r90 top
U12 "AT45DB641E-MWHN" UDFN8-6x5-EP 116.84,62.103 r90 top
U13 "AT45DB641E-MWHN" UDFN8-6x5-EP 123.825,62.103 r90 top
U14 "AT45DB641E-MWHN" UDFN8-6x5-EP 130.81,62.103 r90 top
U15 "FT232RQ" QFN32-5x5-FT232 148.463,60.325 r0 top
U16 "VNC1L-1A" LQFP48-7x7 14.097,25.273 r90 top
VIN "8191-2-5.0" SCREW-TB-2-5.0 80.01,6.35 r0 top
X1 "XTAL_8.000MHz_HEX15" XT-HEX15 62.865,62.357 r90 top
X2 "32.768kHz-NC-306" "Xtal-SMD8.0x3.2 4Pin" 64.643,73.787 r0 top
X3 "XTAL_12.000MHz_STCX15" XT-HEX15 13.97,13.589 r0 top

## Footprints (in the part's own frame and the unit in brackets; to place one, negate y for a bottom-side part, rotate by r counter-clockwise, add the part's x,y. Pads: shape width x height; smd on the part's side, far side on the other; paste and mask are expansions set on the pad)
3296W-THP [mm] "Variable Resistor, Bourns, Straight THP"
  round 1.5 hole 0.8 paste+0 mask+0.05: 1(-2.54,0) 2(0,0) 3(2.54,0)
  silkscreen extent -4.83,-2.41 4.83,2.41, body extent -4.75,-2.43 4.77,2.4, height 11.55
Buzzer-MBS01-12 [mil] "MBS01-12 Dia 12.00mm"
  rect 59x59 hole 35.43: 1(150,0)
  round 59 hole 35.43: 2(-150,0)
  silkscreen extent -240,-240 240,240, body extent -236,-236 236,236, height 374
CAP-EL-SMD-4X5.4 [mil] "CAP El SMD 4x5.4mm"
  rect 106x55 smd mask+1: 1(-70,0) 2(70,0)
  silkscreen extent -70,-105 105,105, body extent -89,-85 93,85, height 213
CAP-EL-SMD-10x10.5 [mm] "CAP El SMD 10.0x10.0mm"
  rect 5x1.4 smd mask+0.025: 1(-4,0) 2(4,0)
  silkscreen extent -5.37,-5.59 5.59,5.59, body extent -5.8,-5.17 5.8,5.13, height 10.21
CAPC0603X85N#1 [mm] "Chip Capacitor, 0603, 2-Leads, Body 1.6x0.8mm, IPC Medium Density"
  rect 1x0.95 smd paste+0 mask+0.05: 1(-0.8,0) 2(0.8,0)
  silkscreen extent -1.55,-0.72 1.55,0.72, body extent -0.8,-0.4 0.8,0.4, height 0.8
CAPC0603X85N#2 [mm] "Chip Capacitor, 0603, 2-Leads, Body 1.6x0.8mm, IPC Medium Density"
  rect 0.9x1 smd paste+0 mask+0.05: 1(-0.85,0) 2(0.85,0)
  silkscreen extent -1.55,-0.72 1.55,0.72, body extent -0.8,-0.4 0.8,0.4, height 0.85
D2PAK [mm] "D2-PAK, 3-Pads, Body 9.4x10.4mm (max), IPC Medium Density"
  rect 3.7x1.3 smd mask+0.025: 1(-6.35,2.54) 3(-6.35,-2.54)
  rect 11.7x10.3 smd mask+0.025: 2(3,0)
  silkscreen extent -3.3,-5.45 9.2,5.45, body extent -7.9,-5.2 7.95,5.2, height 4.6
DIL20-P-2.54 [mil] "DIL20 Way Male 25.4x5.03mm"
  rect 59x59 hole 39.37: 1(-450,-50)
  round 59 hole 39.37: 2(-450,50) 3(-350,-50) 4(-350,50) 5(-250,-50) 6(-250,50) 7(-150,-50) 8(-150,50) 9(-50,-50) 10(-50,50) 11(50,-50) 12(50,50) 13(150,-50) 14(150,50) 15(250,-50) 16(250,50) 17(350,-50) 18(350,50) 19(450,-50) 20(450,50)
  silkscreen extent -515,-115 500,100, body extent -496,-99 500,99, height 323
DIL40-P-2.54 [mil] "DIL40 Way Male 50.8x5.03mm"
  rect 59x59 hole 39.37: 1(-950,-50)
  round 59 hole 39.37: 2(-950,50) 3(-850,-50) 4(-850,50) 5(-750,-50) 6(-750,50) 7(-650,-50) 8(-650,50) 9(-550,-50) 10(-550,50) 11(-450,-50) 12(-450,50) 13(-350,-50) 14(-350,50) 15(-250,-50) 16(-250,50) 17(-150,-50) 18(-150,50) 19(-50,-50) 20(-50,50) 21(50,-50) 22(50,50) 23(150,-50) 24(150,50) 25(250,-50) 26(250,50) 27(350,-50) 28(350,50) 29(450,-50) 30(450,50) 31(550,-50) 32(550,50) 33(650,-50) 34(650,50) 35(750,-50) 36(750,50) 37(850,-50) 38(850,50) 39(950,-50) 40(950,50)
  silkscreen extent -1015,-115 1000,100, body extent -996,-99 1000,99, height 323
DO-213AB [mil] "DO-213AB 5.0x2.5mm"
  rect 55x106 smd mask+1: 1(-95,0) 2(95,0)
  silkscreen extent -155,-70 140,70, body extent -102,-53 102,53, height 106
EL-RAD-12.5x20 [mm] "Capacitor, Electrolytic, THP, Radial, Dia 12.50mm, Pitch 5.00mm"
  rect 1.5x1.5 hole 0.9 paste+0 mask+0.05: 1(0,2.5)
  round 1.5 hole 0.9 paste+0 mask+0.05: 2(0,-2.5)
  silkscreen extent -6.48,-6.48 6.48,6.48, body extent -6.22,-6.29 6.33,6.29, height 20.1
FPC3AMR1-20-B-U [mm] "FPC3AMR1-20-B-U , 1.0mm Pitch Bottom"
  rect 0.5x1.35 smd mask+0.025: 1(-9.5,2) 2(-8.5,2) 3(-7.5,2) 4(-6.5,2) 5(-5.5,2) 6(-4.5,2) 7(-3.5,2) 8(-2.5,2) 9(-1.5,2) 10(-0.5,2) 11(0.5,2) 12(1.5,2) 13(2.5,2) 14(3.5,2) 15(4.5,2) 16(5.5,2) 17(6.5,2) 18(7.5,2) 19(8.5,2) 20(9.5,2)
  rect 1.8x1.5 smd mask+0.025: M1(-11.9,-0.3) M2(11.9,-0.3)
  silkscreen extent -12.3,-1.6 12.3,1.6, body extent -13,-2.65 13,2.5, height 2
HSOP8 [mil] "HSOP 8-Leads, Body 5.0x4.0mm, Pitch 1.27mm"
  rect 70x24 smd paste+0 mask+1.97: 1(-99.49,75) 2(-99.49,25) 3(-99.49,-25) 4(-99.49,-75) 5(99.49,-75) 6(99.49,-25) 7(99.49,25) 8(99.49,75)
  rect 102.36x129.92 smd mask+1: 9(0,0)
  silkscreen extent -145,-98 145,115, body extent -122,-98 122,98, height 70
L0603 [mm] "Ind, 0603, 2-Leads, Body 1.6x0.8mm, IPC Medium Density"
  rect 1x0.95 smd paste+0 mask+0.05: 1(-0.8,0) 2(0.8,0)
  silkscreen extent -1.55,-0.72 1.55,0.72, body extent -0.8,-0.47 0.8,0.48, height 0.78
L0603CS [mm] "Ind, 0603, 2-Leads, Body 1.6x0.8mm, IPC Medium Density"
  rect 1x0.95 smd paste+0 mask+0.05: 1(-0.8,0) 2(0.8,0)
  silkscreen extent -1.55,-0.72 1.55,0.72, body extent -0.9,-0.56 0.9,0.56, height 1.01
LED0805-Green [mm] "LED, 0805, 2-Leads, Body 2.0x1.3mm, IPC Medium Density"
  rect 1.3x1.5 smd paste+0 mask+0.025: 1(-0.85,0) 2(0.85,0)
  silkscreen extent -2.1,-1 1.77,0.99, body extent -1.01,-0.6 1.01,0.65, height 1.2
LED0805-Red [mm] "LED, 0805, 2-Leads, Body 2.0x1.3mm, IPC Medium Density"
  rect 1.3x1.5 smd paste+0 mask+0.025: 1(-0.85,0) 2(0.85,0)
  silkscreen extent -2.1,-1 1.77,0.99, body extent -1.01,-0.6 1.01,0.65, height 1.2
LED0805-Yellow [mm] "LED, 0805, 2-Leads, Body 2.0x1.3mm, IPC Medium Density"
  rect 1.3x1.5 smd paste+0 mask+0.025: 1(-0.85,0) 2(0.85,0)
  silkscreen extent -2.1,-1 1.77,0.99, body extent -1.01,-0.6 1.01,0.65, height 1.2
LF-0157 [mm] "Fuse 0157 6.5x3.7mm"
  rect 2.4x3 smd mask+0.025: 1(-2.4,0) 2(2.4,0)
  silkscreen extent -4,-2.3 4,2.3, body extent -3.4,-1.9 3.4,1.9, height 3.9
LQFP48-7x7 [mil] "LQFP 48 7.0x7.0mm"
  rect 63x12 smd mask+1: 1(-165.35,108.27) 2(-165.35,88.59) 3(-165.35,68.91) 4(-165.35,49.23) 5(-165.35,29.55) 6(-165.35,9.87) 7(-165.35,-9.81) 8(-165.35,-29.49) 9(-165.35,-49.17) 10(-165.35,-68.85) 11(-165.35,-88.53) 12(-165.35,-108.21) 25(165.35,-108.21) 26(165.35,-88.53) 27(165.35,-68.85) 28(165.35,-49.17) 29(165.35,-29.49) 30(165.35,-9.81) 31(165.35,9.87) 32(165.35,29.55) 33(165.35,49.23) 34(165.35,68.91) 35(165.35,88.59) 36(165.35,108.27)
  rect 12x63 smd mask+1: 13(-108.24,-165.32) 14(-88.56,-165.32) 15(-68.88,-165.32) 16(-49.2,-165.32) 17(-29.52,-165.32) 18(-9.84,-165.32) 19(9.84,-165.32) 20(29.52,-165.32) 21(49.2,-165.32) 22(68.88,-165.32) 23(88.56,-165.32) 24(108.24,-165.32) 37(108.24,165.38) 38(88.56,165.38) 39(68.88,165.38) 40(49.2,165.38) 41(29.52,165.38) 42(9.84,165.38) 43(-9.84,165.38) 44(-29.52,165.38) 45(-49.2,165.38) 46(-68.88,165.38) 47(-88.56,165.38) 48(-108.24,165.38)
  silkscreen extent -205,-202 200,203, body extent -177,-177 177,177, height 59
LQFP144-20x20 [mil] "LQFP144 20.0x20.0mm"
  rect 83x12 smd mask+1: 1(-420,342.11) 2(-420,322.43) 3(-420,302.75) 4(-420,283.07) 5(-420,263.39) 6(-420,243.71) 7(-420,224.03) 8(-420,204.35) 9(-420,184.67) 10(-420,164.99) 11(-420,145.31) 12(-420,125.63) 13(-420,105.95) 14(-420,86.27) 15(-420,66.59) 16(-420,46.91) 17(-420,27.23) 18(-420,7.55) 19(-420,-12.13) 20(-420,-31.81) 21(-420,-51.49) 22(-420,-71.17) 23(-420,-90.85) 24(-420,-110.53) 25(-420,-130.21) 26(-420,-149.89) 27(-420,-169.57) 28(-420,-189.25) 29(-420,-208.93) 30(-420,-228.61) 31(-420,-248.29) 32(-420,-267.97) 33(-420,-287.65) 34(-420,-307.33) 35(-420,-327.01) 36(-420,-346.69) 73(422.52,-346.69) 74(422.52,-327.01) 75(422.52,-307.33) 76(422.52,-287.65) 77(422.52,-267.97) 78(422.52,-248.29) 79(422.52,-228.61) 80(422.52,-208.93) 81(422.52,-189.25) 82(422.52,-169.57) 83(422.52,-149.89) 84(422.52,-130.21) 85(422.52,-110.53) 86(422.52,-90.85) 87(422.52,-71.17) 88(422.52,-51.49) 89(422.52,-31.81) 90(422.52,-12.13) 91(422.52,7.55) 92(422.52,27.23) 93(422.52,46.91) 94(422.52,66.59) 95(422.52,86.27) 96(422.52,105.95) 97(422.52,125.63) 98(422.52,145.31) 99(422.52,164.99) 100(422.52,184.67) 101(422.52,204.35) 102(422.52,224.03) 103(422.52,243.71) 104(422.52,263.39) 105(422.52,283.07) 106(422.52,302.75) 107(422.52,322.43) 108(422.52,342.11)
  rect 12x83 smd mask+1: 37(-343.14,-423.55) 38(-323.46,-423.55) 39(-303.78,-423.55) 40(-284.1,-423.55) 41(-264.42,-423.55) 42(-244.74,-423.55) 43(-225.06,-423.55) 44(-205.38,-423.55) 45(-185.7,-423.55) 46(-166.02,-423.55) 47(-146.34,-423.55) 48(-126.66,-423.55) 49(-106.98,-423.55) 50(-87.3,-423.55) 51(-67.62,-423.55) 52(-47.94,-423.55) 53(-28.26,-423.55) 54(-8.58,-423.55) 55(11.1,-423.55) 56(30.78,-423.55) 57(50.46,-423.55) 58(70.14,-423.55) 59(89.82,-423.55) 60(109.5,-423.55) 61(129.18,-423.55) 62(148.86,-423.55) 63(168.54,-423.55) 64(188.22,-423.55) 65(207.9,-423.55) 66(227.58,-423.55) 67(247.26,-423.55) 68(266.94,-423.55) 69(286.62,-423.55) 70(306.3,-423.55) 71(325.98,-423.55) 72(345.66,-423.55) 109(345.66,418.97) 110(325.98,418.97) 111(306.3,418.97) 112(286.62,418.97) 113(266.94,418.97) 114(247.26,418.97) 115(227.58,418.97) 116(207.9,418.97) 117(188.22,418.97) 118(168.54,418.97) 119(148.86,418.97) 120(129.18,418.97) 121(109.5,418.97) 122(89.82,418.97) 123(70.14,418.97) 124(50.46,418.97) 125(30.78,418.97) 126(11.1,418.97) 127(-8.58,418.97) 128(-28.26,418.97) 129(-47.94,418.97) 130(-67.62,418.97) 131(-87.3,418.97) 132(-106.98,418.97) 133(-126.66,418.97) 134(-146.34,418.97) 135(-166.02,418.97) 136(-185.7,418.97) 137(-205.38,418.97) 138(-225.06,418.97) 139(-244.74,418.97) 140(-264.42,418.97) 141(-284.1,418.97) 142(-303.78,418.97) 143(-323.46,418.97) 144(-343.14,418.97)
  silkscreen extent -450,-452 451,448, body extent -432,-436 434,430, height 71
M7395-2 [mil] "M7395 Friction lock Rt Angle 2.54"
  rect 70x70 hole 47.24: 1(50,170)
  round 70 hole 47.24: 2(-50,170)
  silkscreen extent -110,-65 110,220, body extent -100,-395 100,185, height 227
M7395-4 [mil] "M7395 Friction lock Rt Angle 2.54"
  rect 70x70 hole 47.24: 1(150,170)
  round 70 hole 47.24: 2(50,170) 3(-50,170) 4(-150,170)
  silkscreen extent -210,-65 210,220, body extent -200,-395 200,185, height 227
MCX-RT-733660030 [mm] "MCX Rt Angle 733660030 9.5x6.0mm"
  round 2.4 hole 1.4: 1(0,0) 2(2.54,2.54) 3(-2.54,2.54) 4(-2.54,-2.54) 5(2.54,-2.54)
  silkscreen extent -3.17,-3.17 3.17,3.17, body extent -6.5,-3 3,3, height 6.52
QFN32-5x5-FT232 [mil] "QFN 32 5.0x5.0mm"
  oval 35x12 smd paste+0 mask+1: 1(-96.46,68.9) 2(-96.46,49.21) 3(-96.46,29.53) 4(-96.46,9.84) 5(-96.46,-9.84) 6(-96.46,-29.53) 7(-96.46,-49.21) 8(-96.46,-68.9) 17(94.48,-68.9) 18(94.48,-49.21) 19(94.48,-29.53) 20(94.48,-9.84) 21(94.48,9.84) 22(94.48,29.53) 23(94.48,49.21) 24(94.48,68.9)
  oval 12x35 smd paste+0 mask+1: 9(-68.9,-96.45) 10(-49.22,-96.45) 11(-29.53,-96.45) 12(-9.85,-96.45) 13(9.84,-96.45) 14(29.52,-96.45) 15(49.21,-96.45) 16(68.89,-96.45) 25(68.89,94.49) 26(49.21,94.49) 27(29.52,94.49) 28(9.84,94.49) 29(-9.85,94.49) 30(-29.53,94.49) 31(-49.22,94.49) 32(-68.9,94.49)
  rect 125x125 smd paste-1000 mask+1: 33(0,0)
  silkscreen extent -118,-110 106,110, body extent -98,-98 99,98, height 32
REL-D2n [mil] "D2n 10.0x20.0mm"
  rect 70x70 hole 39.37: 1(-150,350)
  round 70 hole 39.37: 4(-150,50) 6(-150,-150) 8(-150,-350) 9(150,-350) 11(150,-150) 13(150,50) 16(150,350)
  silkscreen extent -195,-400 195,400, body extent -197,-398 197,398, height 440
RESC0603X60N [mm] "Chip Resistor, 0603, 2-Leads, Body 1.6x0.8mm, IPC Medium Density"
  rect 0.9x1 smd paste+0 mask+0.05: 1(-0.85,0) 2(0.85,0)
  silkscreen extent -1.55,-0.72 1.55,0.72, body extent -0.8,-0.4 0.8,0.4, height 0.37
RESC1206X71N [mm] "Chip Resistor, 1206, 2-Leads, Body 3.2x1.6mm, IPC Medium Density"
  rect 1.3x1.8 smd paste+0 mask+0.05: 1(-1.5,0) 2(1.5,0)
  silkscreen extent -2.37,-1.15 2.37,1.15, body extent -1.55,-0.78 1.55,0.77, height 0.47
S1216R [mil] "S1216R 12.2x16.0mm"
  rect 71x32 smd mask+1: 1(-222.44,276.18) 2(-222.44,232.87) 3(-222.44,189.57) 4(-222.44,146.26) 5(-222.44,102.95) 6(-222.44,59.65) 7(-222.44,16.34) 8(-222.44,-101.77) 9(-222.44,-145.08) 10(-222.44,-188.39) 11(-222.44,-231.69) 12(-222.44,-275) 13(250,-275) 14(250,-231.69) 15(250,-188.39) 16(250,-145.08) 17(251.97,-102.36) 18(250,16.34) 19(250,59.65) 20(250,102.95) 21(250,146.26) 22(250,189.57) 23(250,232.87) 24(250,276.18)
  silkscreen extent -238,-326 266,327, body extent -226,-315 254,315, height 94
SCREW-TB-2-5.0 [mm] "Screw Terminal 2way 5.0mm"
  rect 2.489x2.489 hole 1.4: 1(-2.5,0)
  round 2.489 hole 1.4: 2(2.5,0)
  silkscreen extent -5,-4.3 5,4.1, body extent -5.57,-4.07 5,4.07, height 10
SCREW-TB-4-5.0 [mm] "Screw Terminal 4way 5.0mm"
  rect 2.489x2.489 hole 1.4: 1(-7.5,0)
  round 2.489 hole 1.4: 2(-2.5,0) 3(2.5,0) 4(7.5,0)
  silkscreen extent -10,-4.3 10,4.1, body extent -10.57,-4.07 10,4.07, height 10
SD-40BD-10 [mil] "SD-40BD-10 14.7x14.5mm"
  rect 28x63 smd mask+1: 1(86.38,250) 2(43.07,250) 3(-0.24,250) 4(-43.54,250) 5(-86.85,250) 6(-130.16,250) 7(-173.46,250) 8(-216.77,250) 9(-260.08,250)
  rect 47x55 smd mask+1: 10(-305.35,230.31)
  rect 63x55 smd mask+1: 11(267.48,230.31)
  rect 47x91 smd mask+1: 12(300.94,-145.67) 13(-307.32,-145.67)
  round 40 hole 39.37 unplated: 14(-197.09,-159.45) 15(117.87,-159.45)
  Top Layer keep-out lines w0.98: -240.16,59.06 122.05,59.06 ; -240.16,35.43 122.05,35.43 ; -240.16,11.81 122.05,11.81 ; -240.16,-15.75 122.05,-15.75 ; -240.16,-39.37 122.05,-39.37 ; -240.16,82.68 -240.16,-66.93 122.05,-66.93 122.05,82.68 -240.16,82.68
  silkscreen extent -296,-317 287,254, body extent -321,-319 317,272, height 73
SDR0805 [mm] "SDR0805 7.8x7.8mm"
  rect 2.7x8 smd mask+0.025: 1(-2.7,0) 2(2.7,0)
  silkscreen extent -4.5,-4.4 4.5,4.4, body extent -3.68,-3.75 3.68,3.75, height 5.05
SIL6P-2.54 [mil] "SIL Strip 2.54mm"
  rect 59x59 hole 39.37: 1(-250,0)
  round 59 hole 39.37: 2(-150,0) 3(-50,0) 4(50,0) 5(150,0) 6(250,0)
  silkscreen extent -310,-50 300,50, body extent -296,-49 300,49, height 323
SIL7P-2.54 [mil] "SIL Strip 2.54mm"
  rect 59x59 hole 39.37: 1(-300,0)
  round 59 hole 39.37: 2(-200,0) 3(-100,0) 4(0,0) 5(100,0) 6(200,0) 7(300,0)
  silkscreen extent -360,-50 350,50, body extent -346,-49 350,49, height 323
SIL8P-2.54 [mil] "SIL Strip 2.54mm"
  rect 59x59 hole 39.37: 1(-350,0)
  round 59 hole 39.37: 2(-250,0) 3(-150,0) 4(-50,0) 5(50,0) 6(150,0) 7(250,0) 8(350,0)
  silkscreen extent -410,-50 400,50, body extent -396,-49 400,49, height 323
SMC [mm] "Molded Diode, 2-Leads, Body 6.9x5.8mm, IPC Medium Density"
  rect 2.8x3.8 smd mask+0.025: 1(-3.57,0) 2(3.57,0)
  silkscreen extent -5.8,-3.3 5.3,3.3, body extent -3.9,-2.95 4.05,2.95, height 2.3
SO8 [mm] "SOIC, 8-Leads, Body 5.0x4.0mm (max), Pitch 1.27mm, IPC Medium Density"
  rect 2.2x0.6 smd paste+0 mask+0.05: 1(-2.4,1.905) 2(-2.4,0.635) 3(-2.4,-0.635) 4(-2.4,-1.905) 5(2.4,-1.905) 6(2.4,-0.635) 7(2.4,0.635) 8(2.4,1.905)
  silkscreen extent -2.52,-2.5 0.9,2.78, body extent -3.1,-2.5 3.1,2.5, height 1.78
SO16 [mm] "SOIC, 16-Leads, Body 10.28.8x4.0mm (max), Pitch 1.27mm"
  rect 2.413x0.711 smd mask+0.025: 1(-2.525,4.45) 2(-2.525,3.18) 3(-2.525,1.91) 4(-2.525,0.64) 5(-2.525,-0.63) 6(-2.525,-1.9) 7(-2.525,-3.17) 8(-2.525,-4.44) 9(2.555,-4.44) 10(2.555,-3.17) 11(2.555,-1.9) 12(2.555,-0.63) 13(2.555,0.64) 14(2.555,1.91) 15(2.555,3.18) 16(2.555,4.45)
  silkscreen extent -2.97,-5.07 0.64,5.42, body extent -3.03,-5 3.05,5, height 1.65
SOD80 [mm] "Diode, SOD80 2-Leads, Body 3.5x1.4mm, IPC Medium Density"
  rect 1.2x1.75 smd paste+0 mask+0.025: 1(1.65,0) 2(-1.65,0)
  silkscreen extent -2.5,-1.1 3.05,1.1, body extent -1.85,-0.8 1.85,0.8, height 1.61
SOT23 [mm] "SOT23, 3-Leads, Body 3.0x2.6mm (max), Pitch 0.95mm, IPC Medium Density"
  rect 1.3x0.6 smd paste+0 mask+0.05: 1(-1.05,0.95) 2(-1.05,-0.95) 3(1.05,0)
  silkscreen extent -1.95,-1.75 1.95,1.75, body extent -1.56,-1.5 1.58,1.5, height 1
T491-A [mm] "Tant Capacitor, 2-Leads, Body 3.2x1.6mm, IPC Medium Density"
  rect 1.95x1.25 smd mask+0.025: 1(-1.225,0) 2(1.225,0)
  silkscreen extent -2.45,-1.15 2.45,1.15, body extent -1.6,-0.8 1.59,0.8, height 1.61
T491-D [mil] "Tant Capacitor, 2-Leads, Body 7.3x4.3mm, IPC Medium Density"
  rect 105x140 smd mask+0.98: 1(-125,0) 2(125,0)
  silkscreen extent -200,-100 200,100, body extent -144,-85 144,85, height 111
TO-92 [mm] "TO-92"
  round 1.2 hole 0.7 paste-2 mask+0.05: 1(-1.27,0.254) 2(0,1.5) 3(1.27,0.254)
  silkscreen extent -2.52,-1.2 2.52,2.93, body extent -2.4,-1.28 2.4,2.65, height 6.7
TP-THP-0.7mm [mm] "Test Point, THP, 0.7mm"
  round 1.2 hole 0.7 paste-1 mask+0.05: 1(0,0)
  silkscreen extent -0.75,-0.75 0.75,0.75, body extent -0.5,-0.5 0.5,0.5, height 0.1
UDFN8-6x5-EP [mil] "UDFN 6.0x5.0mm"
  rect 50x25 smd: 1(-110,75) 2(-110,25) 3(-110,-25) 4(-110,-75) 5(110,-75) 6(110,-25) 7(110,25) 8(110,75)
  rect 140x165 smd: 9(0,0)
  silkscreen extent -155,-105 145,105, body extent -120,-98 120,98, height 24
XT-HEX15 [mm] "XTAL-HEX15, 2-Leads, Body 11.1x4.83mm (max), Pitch 4.3mm"
  rect 5.5x1.5 smd paste+0 mask+0.025: 1(-4.25,0) 2(4.25,0)
  silkscreen extent -5.7,-2.6 5.7,2.6, body extent -6.15,-2.25 6.15,2.25, height 5.18
"Xtal-SMD8.0x3.2 4Pin" [mil] "Xtal SMD 8.0x3.2mm"
  rect 67x75 smd: 1(-108,-62) 2(107,-62) 3(107,63) 4(-108,63)
  silkscreen extent -192,-107 177,108, body extent -158,-75 157,75, height 96

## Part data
ANT: library part Coax-MCX-73366-0030, "Connector Coax MCX Rt Angle 50Ohm"
BUZ1: library part BUZZER_MBS-03_THP, "Buzzer Magnetic"
C1: library part 1000uF_35V_20%_V-YXF, "Cap Electrolytic THP Radial - Low Imp"
C2 C3: library part 100uF-35V-20%-EEVFC_V, "Cap Electrolytic SMD Low Imp"
C4 C7: library part 470uF-35V-20%-LZ_V, "Cap Electrolytic SMD Low Imp"
C5 C8: library part 22nF_0603N_50V_10%_X7R_V, "Cap Ceramic X7R"
C6 C9: library part 220pF_0603N_50V_10%_NP0_V, "Cap Ceramic NP0"
C10 C14 C30 C69 C86: library part 10uF_6.3V_CASE-A_20%_V, "Cap Tantalum Case-A"
C11 C15 C22 C70 C80 C87: library part 1nF_0603N_50V_10%_X7R_V, "Cap Ceramic X7R"
C12 C16 C18 C20 C24 C26 C28 C49 C51 C52 C54 C58 C62 C65 C71 C83 C88: library part 10nF_0603N_50V_10%_X7R_V, "Cap Ceramic X7R"
C13 C17 C19 C21 C23 C25 C27 C29 C35 C36 C38 C39 C40 C41 C44 C46 C48 C53 C55 C57 C61 C66 C68 C72 C73 C74 C75 C76 C77 C82 C89 C90: library part 100nF_0603N_50V_5%_X7R_V, "Cap Ceramic X7R"
C31 C32: library part 15pF_0603N_50V_5%_NP0_V, "Cap Ceramic NP0"
C33 C34 C43 C45: library part DNF_0603N_50V_10%_X7R_V, "Cap Ceramic X7R - Do not Fit"
C37 C42: library part 150pF_0603N_50V_5%_NP0_V, "Cap Ceramic NP0"
C47: library part 2.2uF-50V-20%_4x5.4_V, "Cap Electrolytic SMD (4x5.4)"
C50 C64: library part 4.7uF_6V_CASE-A_20%_V, "Cap Tantalum Case-A"
C78 C79: library part 47pF_0603N_50V_10%_NP0_V, "Cap Ceramic NP0"
C81: library part 47uF_25V_CASE-D_20%_V, "Cap Tantalum Case-D"
C84 C85: library part 10pF_0603N_50V_5%_NP0_V, "Cap Ceramic NP0"
D1 D5 D8: library part ER3M_SMC_H, "Diode Rectifier (1000V 3A)"
D2 D19: library part BAS16_SOT23-3N_V, "Diode Small Signal"
D3: library part FUSE_0157003.DRT_3.0AMP, "Fuse Clip and Nano Fuse"
D4 D7 D9: library part SMCJ26A_V, "TVS 1500W SMC"
D6 D10: library part SMS2100_V, "Diode Schottky Rectifier 2Amp 100V"
D11 D12: library part SM4007_V, "Diode Rectifier 1Amp 1000V"
D13 D14: library part SM4007_V-DNF, "Diode Rectifier 1Amp 1000V - Do not Fit"
D15 D16 D17 D18 D20 D21 D22 D23 D25: library part LL4148_MELF_H, "Diode Fast Switching Surface Mount"
D24: library part LL4148_MELF_X, "Diode Fast Switching Surface Mount"
GPS1: library part "S1216R GPS Receiver", "Module GPS Receiver"
ICD P1 P2: "Header SIL Male THP, 2.54mm Pitch"
J5 J7 VIN: "Screw Terminal 5.0mm Pitch"
J8 J11 J14: "Header Pluggable 2.54mm Rt Angle Friction Lock"
K1 K2: "Relay DPDT 12V 3A"
L1 L2: library part 33uH_SDR0805_H, "Inductor Power"
L3 L4 L5 L6 L7 L9: library part 100nH_CI160808_H, "Inductor Chip SMD"
L8: library part 33nH_0603CS_5%_H, "Inductor Chip SMD"
LCD1: "ZIF Connector, 1.0mm Contact Pitch Bottom"
LCD-SPR1 LCD-SPR2: "Test Point Through Hole Plated 0.7mm Hole"
LED1: library part RED_0805_SMD_V, "LED SMD 0805 Red"
LED2: library part GREEN_0805_SMD_V, "LED SMD 0805 Green"
LED3: library part YELLOW_0805_SMD_V, "LED SMD 0805 Yellow"
LED4: library part RED_0805_SMD_H, "LED SMD 0805 Red"
LED5: library part GREEN_0805_SMD_H, "LED SMD 0805 Green"
P3 P4 P5: "Header Male Straight, 2.54mm Pitch - Do not Fit"
Q1 Q2 Q3 Q5 Q8 Q9 Q11 Q12 Q13 Q16 Q17 Q18 Q20 Q21 Q22: library part BC817_SOT23, "Transistor NPN General Purpose"
Q4 Q6 Q7 Q10: library part BC817_SOT23-DNF, "Transistor NPN General Purpose - Do not Fit"
Q13X: library part BC337_TO-92-DNF, "Transistor NPN Amplifier - Do not Fit"
Q14: library part IRF9530NS_D2PAK, "FET P-Channel 14A 100V"
Q15 Q19: library part BC807_SOT23-3N, "Transistor PNP General Purpose"
Q15X: library part BC327_TO-92-DNF, "Transistor PNP Amplifier - Do not Fit"
R1 R3 R7 R14 R18 R27 R43 R56 R59 R71 R72 R73 R74 R75 R76 R77 R78 R79 R80 R81 R82 R83 R84 R85 R86 R88 R90 R94 R96 R100 R101 R102 R104 R105 R107 R121 R122: library part 10K_0603_V, "Resistor Chip SMD"
R2 R8: library part 470R_0603_V, "Resistor Chip SMD"
R4 R11: library part 4K7_0603_V, "Resistor Chip SMD"
R5 R12 R47 R48 R60 R61: library part 3K3_0603_V, "Resistor Chip SMD"
R6 R17 R25 R41 R53 R67 R93 R95 R97 R99 R103 R106: library part 2K2_0603_H, "Resistor Chip SMD"
R9: library part 5K6_0603_V, "Resistor Chip SMD"
R10 R13: library part DNF_0603_V, "Resistor Chip SMD - Do not Fit"
R15: library part 0R_0603_V-DNF, "Resistor Chip SMD - Do not Fit"
R16 R92 R109 R117: library part 0R_0603_V, "Resistor Chip SMD"
R19: library part 1M_0603_H, "Resistor Chip SMD"
R20 R21 R28 R29 R36 R37: library part 1K8_0603_H, "Resistor Chip SMD"
R22 R23 R30 R31 R38 R39: library part 1K_0603_H, "Resistor Chip SMD"
R24 R34 R40: library part 1K_0603_V, "Resistor Chip SMD"
R26 R42: library part 390R_0603_H, "Resistor Chip SMD"
R32 R33 R44 R45 R51 R52 R63 R64: library part DNP_0603_H, "Resistor Chip SMD"
R35 R46 R55 R66 R110 R116: library part DNP_0603_V, "Resistor Chip SMD"
R49 R54 R62 R68: library part 560R_0603_V, "Resistor Chip SMD"
R50 R65: library part 120R_1206_V-DNF, "Resistor Chip SMD - Do not Fit"
R57 R69 R123: library part 0R_0603_H, "Resistor Chip SMD"
R58 R70 R91 R98: library part 4K7_0603_H, "Resistor Chip SMD"
R87: library part 10K_3296W-1-103_THP_V, "Variable Resistor THP"
R89: library part 10R_1206_H, "Resistor Chip SMD"
R108: library part 10K_0603_H, "Resistor Chip SMD"
R111 R113: library part 27R_0603_H, "Resistor Chip SMD"
R112 R114 R115: library part 47K_0603_H, "Resistor Chip SMD"
R118: library part 180R_0603_V, "Resistor Chip SMD"
R119 R120: library part 330R_0603_H, "Resistor Chip SMD"
R124 R125 R126 R127 R128 R129: library part 15R_1206_H, "Resistor Chip SMD"
R130 R131 R132 R133: library part 0r_0603_H, "Resistor Chip SMD"
SD1: "SD Micro Push-Push"
U1 U2: "IC Switching Regulator 2.5A"
U3: library part PIC24EP512GU814-I/PL_LQFP144, "IC Microcontroller 16-Bit and Digital Signal Controller"
U4 U5: library part DS75176BM_SO8, "IC 3.3V RS-485 Drivers and Receivers"
U6 U8 U9 U10 U11 U12 U13 U14: library part AT45DB641E-MWHN_UDFN, "IC 64Mbit Dual-IF Dataflash"
U7: library part 74LVC138AD_SO16, "IC 3-Line to 8-Line Decoder / Demultplexer"
U15: library part FT232RQ_QFN32, "IC USB UART"
U16: library part VNC1L-1A-LQFP48, "IC Dual USB Host Controller"
X1 X3: "Crystal - HEX15"
X2: library part XTAL_32.768kHz-NC-306, "Crystal - NC-306 (12pF)"

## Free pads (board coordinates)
  round 8 hole 3.5: 0(4,105) 1(4,4) 2(156,4) 3(156,105)
  round 1.5 smd paste+0 mask+0.05: 1(10.668,106.172) 1(23.935,2.246) 1(149.86,106.172)

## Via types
v1: diameter 0.7, hole 0.3, Top Layer to Bottom Layer, tented both sides, 515 vias

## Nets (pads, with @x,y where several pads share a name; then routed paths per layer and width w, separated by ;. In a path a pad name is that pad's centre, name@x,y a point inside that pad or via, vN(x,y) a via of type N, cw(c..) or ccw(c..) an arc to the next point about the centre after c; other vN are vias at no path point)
3V3: C7.1 L2.2 L3.1 L4.1 L9.2 P3.7 P3.8 P4.7 P4.8 R8.1 R9.1 R10.1 | length 61.5
  Top Layer w0.508: L4.1@31.026,14.351 40.64,14.351 42.672,16.383 v1(53.721,16.383) ; L3.1@78.397,47.371 v1(79.502,47.371) ; v1(83.693,45.212) 83.756,45.275 C7.1@85.09,45.275 86.551,45.275 v1(86.614,45.212) ; v1(90.805,44.704) 93.091,44.704 93.091,40.181 93.56,39.712 R8.1@93.56,38.735 R9.1@95.67,38.735 R10.1@95.67,37.211 ; v1(127.508,24.892) 127.546,24.854 L9.2@128.778,24.854
  Bottom Layer w0.508: v1(53.721,16.383) 69.215,16.383 70.358,17.526 v1(73.787,17.526)
3V3A: C22.1 C23.1 L5.1 U3.41 | length 8.1
  Top Layer w0.203: L5.1@36.449,45.339 L5.1@36.576,45.212
  Top Layer w0.254: L5.1@36.449,45.339 36.449,48.387 C23.1@36.487,48.387 37.211,48.387 39.131,50.307 U3.41@39.131,51.726
3V3UC: C10.1 C11.1 C12.1 C13.1 C18.1 C19.1 C20.1 C21.1 C24.1 C25.1 C26.1 C27.1 C28.1 C29.1 C47.1 C48.1 C49.1 C51.1 C53.1 C54.1 C57.1 C58.1 C61.1 C62.1 C90.1 ICD.2 L3.2 L5.2 R14.1 R74.1 R92.1 R121.1 R122.1 SD1.4 U3.2 U3.24 U3.52 U3.64 U3.89 U3.112 U3.124 U6.6 U7.6 U7.16 U8.6 U9.6 U10.6 U11.6 U12.6 U13.6 U14.6 | length 92.6
  Top Layer w0.203: C20.1@32.004,59.182 32.893,59.182 33.387,59.676 U3.24@35.179,59.676 ; C18.1@32.131,70.866 32.258,70.993 32.893,70.993 33.212,70.674 U3.2@35.179,70.674 ; U3.52@44.629,51.726 44.629,50.113 45.339,49.403 C24.1@45.339,48.387 ; U3.124@47.129,73.126 47.129,74.434 47.625,74.93 C28.1@47.625,75.819 ; U3.64@50.628,51.726 50.628,49.829 51.308,49.149 C26.1@51.308,48.387 ; v1(53.086,71.12) 53.127,71.161 U3.112@53.127,73.126 ; v1(54.356,61.722) 54.402,61.676 U3.89@56.579,61.676
  Top Layer w0.508: v1(25.4,39.116) 25.439,39.155 R92.1@26.67,39.155 ; v1(29.464,59.182) 29.502,59.144 C21.1@30.607,59.144 ; v1(29.464,70.993) 29.502,70.955 C19.1@30.607,70.955 ; C21.1@30.645,59.144 C20.1@32.131,59.144 ; C19.1@30.696,70.955 C18.1@32.131,70.955 ; R14.1@31.965,43.561 31.965,44.792 v1(32.004,44.831) ; v1(33.655,45.339) L5.2@34.887,45.339 ; C25.1@45.25,46.863 45.25,45.682 v1(45.339,45.593) ; C25.1@45.25,46.901 C24.1@45.25,48.387 ; C28.1@47.663,75.819 C29.1@47.663,77.343 47.663,78.651 v1(47.752,78.74) ; v1(51.181,45.72) 51.219,45.758 C27.1@51.219,46.863 ; C27.1@51.219,46.901 C26.1@51.219,48.387 ; v1(68.834,54.61) 68.839,54.615 U7.6@70.5,54.615 ; C10.1@69.977,47.453 v1(69.977,49.149) ; C13.1@72.009,47.409 v1(72.009,48.641) ; C12.1@73.533,47.409 v1(73.533,48.641) ; v1(75.057,48.641) C11.1@75.057,47.409 75.057,47.371 L3.2@76.797,47.371 ; R74.1@75.145,50.165 v1(76.454,50.165) ; U7.16@75.58,60.965 75.58,63.358 76.82,63.358 v1(76.835,63.373) ; U6.6@82.555,65.201 82.55,65.206 82.55,67.945 v1(83.947,67.945) ; U8.6@89.54,65.201 C49.1@89.54,67.823 ; C49.1@89.7,67.945 v1(90.932,67.945) ; U9.6@96.525,65.201 96.52,65.206 96.52,67.945 v1(97.917,67.945) ; U10.6@103.51,65.201 103.505,65.206 103.505,67.945 v1(104.902,67.945) ; U11.6@110.495,65.201 110.49,65.206 110.49,67.945 v1(111.887,67.945) ; U12.6@117.48,65.201 C58.1@117.48,67.823 ; C58.1@117.64,67.945 v1(118.872,67.945) ; U13.6@124.465,65.201 C61.1@124.465,67.823 ; C61.1@124.625,67.945 v1(125.857,67.945) ; U14.6@131.45,65.201 C62.1@131.45,67.823 ; C62.1@131.61,67.945 v1(132.842,67.945) ; C47.1@134.62,90.678 v1(134.62,92.837) ; v1(137.16,89.662) 137.197,89.699 SD1.4@140.97,89.699 ; v1(138.43,82.423) R121.1@138.43,83.605 ; R122.1@138.43,94.83 v1(138.43,96.012)
3V3USB: C14.1 C15.1 C16.1 C17.1 C73.1 C74.1 C75.1 C76.1 C77.1 L4.2 L6.1 LED4.2 LED5.2 P2.7 R105.1 R108.1 R109.1 R110.1 U16.2 U16.17 U16.30 U16.40 | length 57.4
  Top Layer w0.254: C76.1@7.023,26.67 8.128,26.67 v1(8.382,26.416) 8.489,26.523 U16.40@9.896,26.523 ; v1(8.255,20.574) 8.89,19.939 11.684,19.939 11.847,20.102 U16.2@11.847,21.073 ; U16.30@14.346,29.473 14.346,32.347 14.346,32.38 C75.1@14.351,32.385 ; U16.17@18.296,24.523 20.078,24.523 v1(20.32,24.765) C74.1@21.425,24.765 C74.1@21.463,24.765 ; v1(20.32,23.114) C77.1@21.425,23.114
  Top Layer w0.508: v1(1.143,23.622) R110.1@2.198,23.622 ; v1(1.143,26.67) R109.1@2.198,26.67 ; v1(3.556,17.018) 3.594,16.98 L6.1@4.826,16.98 ; C73.1@7.023,20.574 v1(8.255,20.574) ; v1(13.335,32.385) 13.373,32.347 14.346,32.347 C75.1@14.351,32.347 ; LED5.2@26.885,22.86 v1(28.194,22.86) ; LED4.2@26.885,26.67 v1(28.194,26.67) ; C15.1@26.924,14.351 C14.1@26.924,19.304 ; C15.1@26.962,14.351 L4.2@29.337,14.351 ; C14.1@27.006,19.431 28.956,19.431 P2.7@29.845,20.32 35.052,20.32 35.814,21.082 v1(35.814,22.86) ; R105.1@33.87,35.56 34.798,35.56 35.052,35.306 35.052,26.035 35.814,25.273 v1(35.814,22.86) ; R108.1@34.505,22.86 v1(35.814,22.86)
